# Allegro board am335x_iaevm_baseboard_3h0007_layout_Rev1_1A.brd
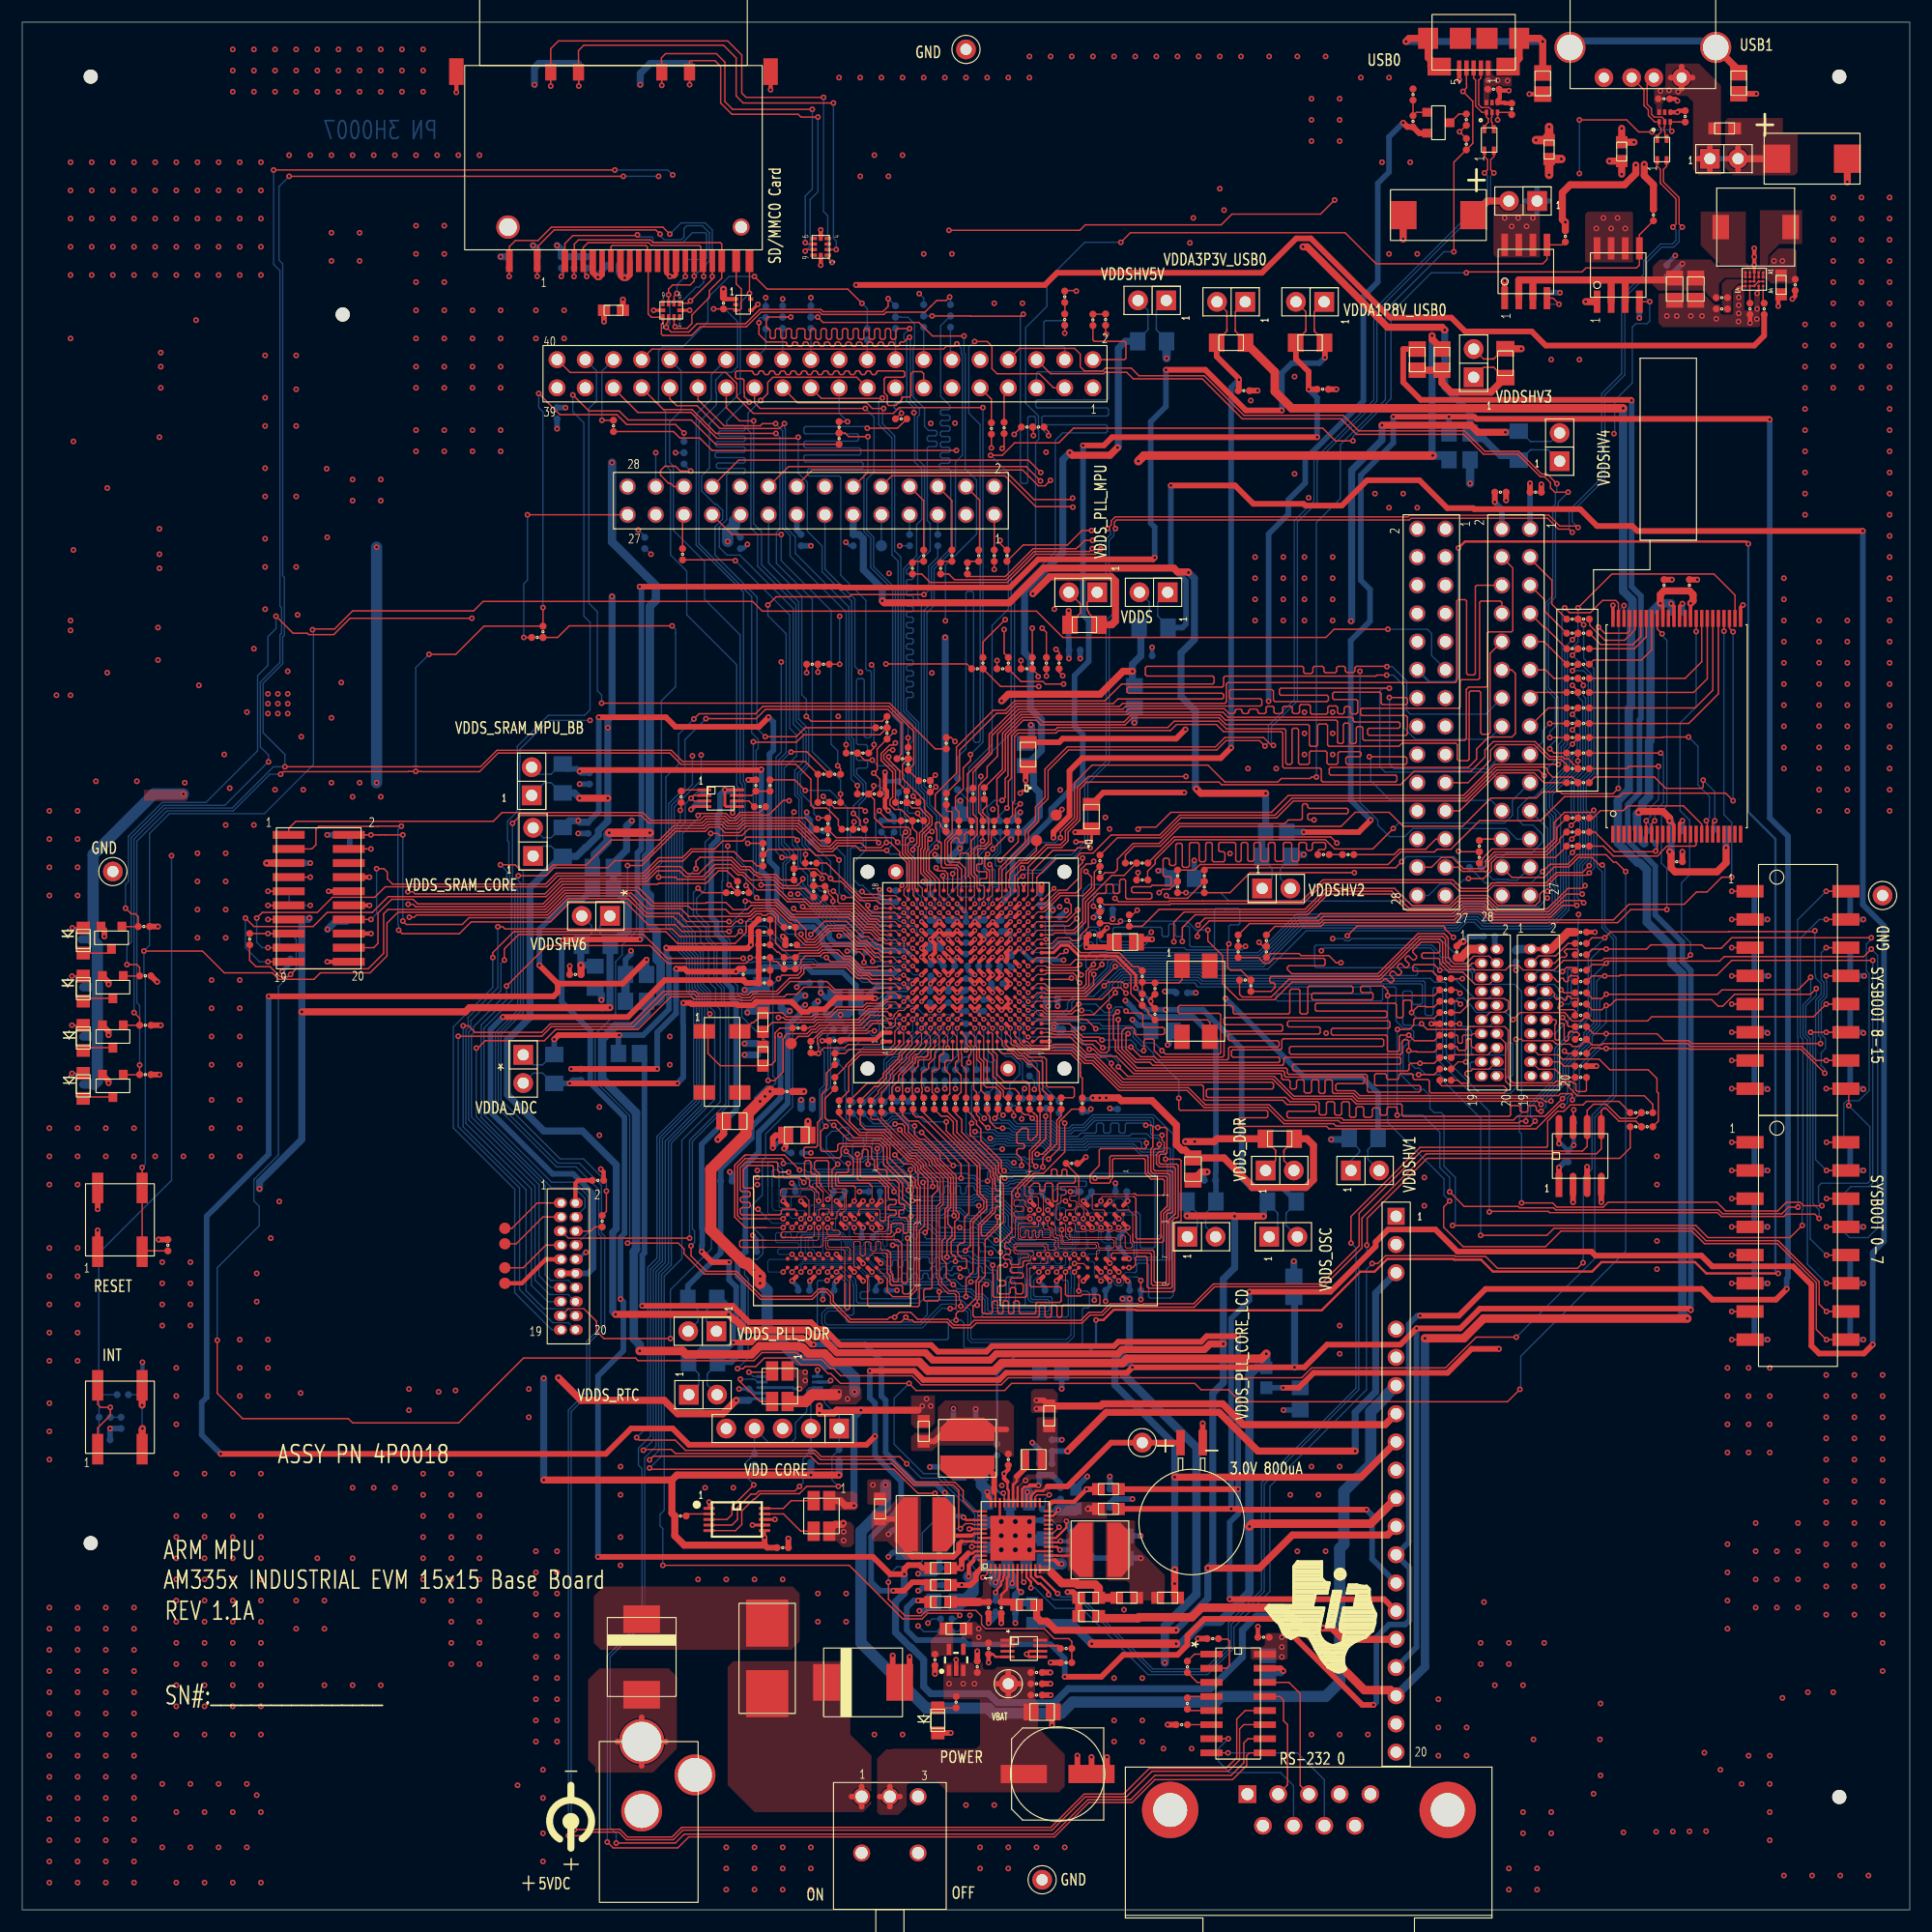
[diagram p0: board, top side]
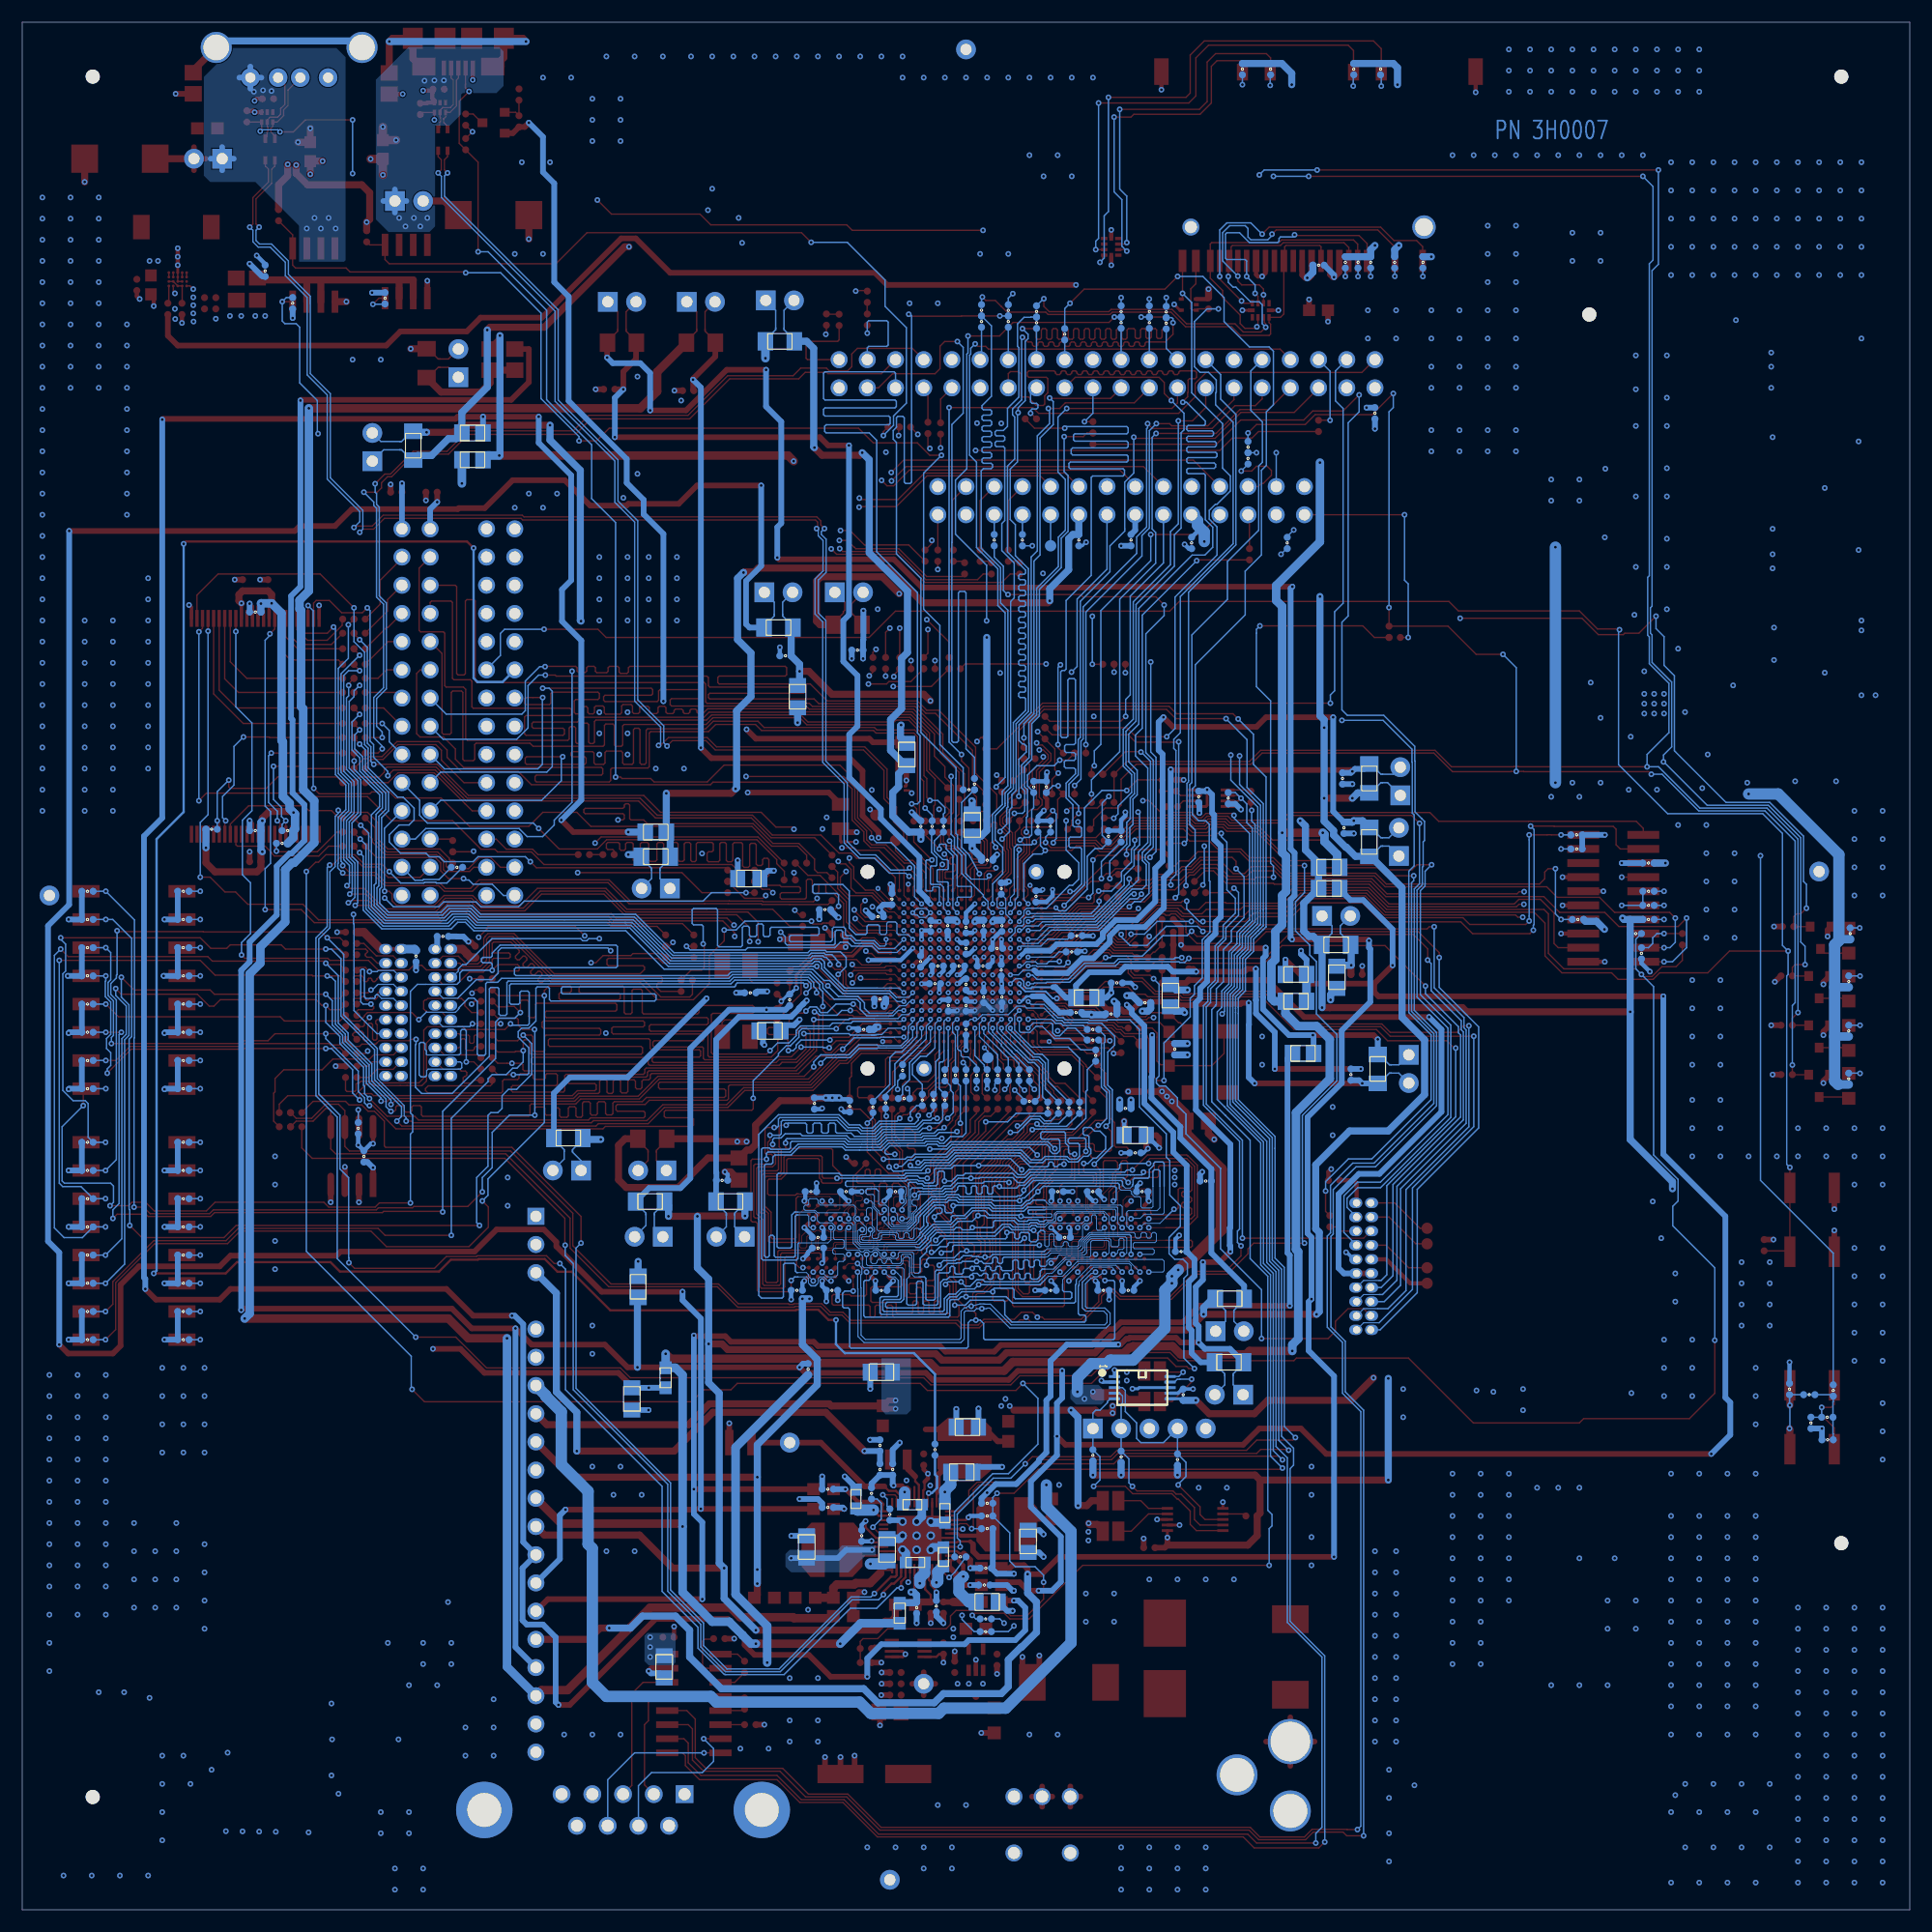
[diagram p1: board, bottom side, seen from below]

Outline 170 x 170 mm; copper layers: TOP, LY2_GND, LY3, LY4, LY5_GND, BOTTOM. Coordinates in mm from the lower left corner of the outline.
Outline path: 0,170 0,0 170,0 170,170 0,170

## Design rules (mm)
net group AM335X_DDR_A0: nets AM335X_DDR_A0 DDR_A0
net group AM335X_DDR_A1: nets AM335X_DDR_A1 DDR_A1
net group AM335X_DDR_A2: nets AM335X_DDR_A2 DDR_A2
net group AM335X_DDR_A3: nets AM335X_DDR_A3 DDR_A3
net group AM335X_DDR_A4: nets AM335X_DDR_A4 DDR_A4
net group AM335X_DDR_A5: nets AM335X_DDR_A5 DDR_A5
net group AM335X_DDR_A6: nets AM335X_DDR_A6 DDR_A6
net group AM335X_DDR_A7: nets AM335X_DDR_A7 DDR_A7
net group AM335X_DDR_A8: nets AM335X_DDR_A8 DDR_A8
net group AM335X_DDR_A9: nets AM335X_DDR_A9 DDR_A9
net group AM335X_DDR_A10: nets AM335X_DDR_A10 DDR_A10
net group AM335X_DDR_A11: nets AM335X_DDR_A11 DDR_A11
net group AM335X_DDR_A12: nets AM335X_DDR_A12 DDR_A12
net group AM335X_DDR_A13: nets AM335X_DDR_A13 DDR_A13
net group AM335X_DDR_A14: nets AM335X_DDR_A14 DDR_A14
net group AM335X_DDR_BA0: nets AM335X_DDR_BA0 DDR_BA0
net group AM335X_DDR_BA1: nets AM335X_DDR_BA1 DDR_BA1
net group AM335X_DDR_BA2: nets AM335X_DDR_BA2 DDR_BA2
net group AM335X_DDR_CASN: nets AM335X_DDR_CASN DDR_CASN
net group AM335X_DDR_CKE: nets AM335X_DDR_CKE DDR_CKE
net group AM335X_DDR_CLK: nets AM335X_DDR_CLK DDR_CLK
net group AM335X_DDR_CLKN: nets AM335X_DDR_CLKN DDR_CLKN
net group AM335X_DDR_CSN: nets AM335X_DDR_CSN DDR_CSN
net group AM335X_DDR_D0: nets AM335X_DDR_D0 DDR_D0
net group AM335X_DDR_D1: nets AM335X_DDR_D1 DDR_D1
net group AM335X_DDR_D2: nets AM335X_DDR_D2 DDR_D2
net group AM335X_DDR_D3: nets AM335X_DDR_D3 DDR_D3
net group AM335X_DDR_D4: nets AM335X_DDR_D4 DDR_D4
net group AM335X_DDR_D5: nets AM335X_DDR_D5 DDR_D5
net group AM335X_DDR_D6: nets AM335X_DDR_D6 DDR_D6
net group AM335X_DDR_D7: nets AM335X_DDR_D7 DDR_D7
net group AM335X_DDR_D8: nets AM335X_DDR_D8 DDR_D8
net group AM335X_DDR_D9: nets AM335X_DDR_D9 DDR_D9
net group AM335X_DDR_D10: nets AM335X_DDR_D10 DDR_D10
net group AM335X_DDR_D11: nets AM335X_DDR_D11 DDR_D11
net group AM335X_DDR_D12: nets AM335X_DDR_D12 DDR_D12
net group AM335X_DDR_D13: nets AM335X_DDR_D13 DDR_D13
net group AM335X_DDR_D14: nets AM335X_DDR_D14 DDR_D14
net group AM335X_DDR_D15: nets AM335X_DDR_D15 DDR_D15
net group AM335X_DDR_DQM0: nets AM335X_DDR_DQM0 DDR_DQM0
net group AM335X_DDR_DQM1: nets AM335X_DDR_DQM1 DDR_DQM1
net group AM335X_DDR_DQS0: nets AM335X_DDR_DQS0 DDR_DQS0
net group AM335X_DDR_DQS1: nets AM335X_DDR_DQS1 DDR_DQS1
net group AM335X_DDR_DQSN0: nets AM335X_DDR_DQSN0 DDR_DQSN0
net group AM335X_DDR_DQSN1: nets AM335X_DDR_DQSN1 DDR_DQSN1
net group AM335X_DDR_RASN: nets AM335X_DDR_RASN DDR_RASN
net group AM335X_DDR_WEN: nets AM335X_DDR_WEN DDR_WEN
net group AM335X_DDRODT: nets AM335X_DDRODT DDR_ODT
net group DP5: nets USB1_DM USB1_DP
net group JTAG: nets JTAG_TDI JTAG_TDO
net group 54: nets AM335X_GPMC_AD10 AM335X_GPMC_AD11 AM335X_LCD_DATA0 AM335X_LCD_DATA1 AM335X_LCD_DATA2 AM335X_LCD_DATA3 AM335X_LCD_DATA4 AM335X_LCD_DATA5 AM335X_LCD_DATA6 AM335X_LCD_DATA7 AM335X_LCD_DATA8 AM335X_LCD_DATA9 AM335X_LCD_DATA10 AM335X_LCD_DATA11 AM335X_LCD_DATA12 AM335X_LCD_DATA13 AM335X_LCD_DATA14 AM335X_LCD_DATA15 AM335X_LCD_HSYNC AM335X_LCD_PCLK AM335X_LCD_VSYNC
net group 69: nets AM335X_MII1_RXD0 AM335X_MII1_RXD1 AM335X_MII1_RXD2 AM335X_MII1_RXD3 AM335X_MII1_RXDV AM335X_MII1_TXD0 AM335X_MII1_TXD1 AM335X_MII1_TXD2 AM335X_MII1_TXD3 AM335X_MII1_TXEN
net group 69_CNTRL: nets AM335X_MII1_RXCLK AM335X_MII1_TXCLK EXP_MII1_RXCLK EXP_MII1_TXCLK
net group 69B: nets EXP_MII1_REFCLK EXP_MII1_RXD0 EXP_MII1_RXD1 EXP_MII1_RXD2 EXP_MII1_RXD3 EXP_MII1_RXDV EXP_MII1_TXD0 EXP_MII1_TXD1 EXP_MII1_TXD2 EXP_MII1_TXD3 EXP_MII1_TXEN
net group 70: nets AM335X_MII1_MDIO_CLK AM335X_MII1_MDIO_DATA EXP_MII1_MDIO_CLK EXP_MII1_MDIO_DATA
net group 80: nets AM335X_GPMC_A1 AM335X_GPMC_A2 AM335X_GPMC_A3 AM335X_GPMC_BE1N AM335X_GPMC_CLK AM335X_GPMC_CS3N
net group 81: nets EXP_GPMC_BE1N EXP_GPMC_CLK EXP_GPMC_CS3N GPMC_A1 GPMC_A2 GPMC_A3 SDIO_GPMC_BE1N SDIO_GPMC_CLK SDIO_GPMC_CS3N
net group 92: nets AM335X_GPMC_A0 AM335X_GPMC_A4 AM335X_GPMC_A6 AM335X_GPMC_A11 GPMC_A0 GPMC_A4 GPMC_A5 GPMC_A6 GPMC_A7 GPMC_A8 GPMC_A9 GPMC_A10 GPMC_A11
net group EXP_MMC0: nets EXP_MMC0_CLK EXP_MMC0_CMD EXP_MMC0_DAT0 EXP_MMC0_DAT1 EXP_MMC0_DAT2 EXP_MMC0_DAT3
net group H_SDMMC2: nets EXP_MMC1_CLK EXP_MMC1_CMD EXP_MMC1_DAT0 EXP_MMC1_DAT1 EXP_MMC1_DAT2 EXP_MMC1_DAT3 EXP_MMC1_DAT4 EXP_MMC1_DAT5 EXP_MMC1_DAT6 EXP_MMC1_DAT7
net group POWER_TRACE: nets VDDSHV1
net group SD_MMC_CC: nets MMC_CLK MMC_CMD MMC_D0 MMC_D1 MMC_D2 MMC_D3 MMC_D4 MMC_D5 MMC_D6 MMC_D7
net group USB: nets USB0_CONN_DM USB0_CONN_DP USB0_DM USB0_DP USB1_CONN_DM USB1_CONN_DP
nets with their own width: min track width 0.381; nets VDDSHV4 VDDSHV6

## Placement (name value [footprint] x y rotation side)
BT1  CoinBattery3.1V  [MS920SE-FL27E]  105.32 42.07 90 top
C1  0.01uF  [SM-7351-CAP-0402]  64.05 100.24 270 bottom
C2  25pF  [SM-7351-CAP-0603]  66.71 79.92 90 top
C3  25pF  [SM-7351-CAP-0603]  66.71 76.87 270 top
C4  18pF  [SM-7351-CAP-0402]  102.02 80.66 90 top
C5  18pF  [SM-7351-CAP-0402]  102.02 82.97 270 top
C9  0.1uF  [SM-7351-CAP-0402]  68.62 85.25 270 top
C10  0.001uF  [SM-7351-CAP-0402]  69.63 85.25 270 top
C11  0.1uF  [SM-7351-CAP-0402]  66.84 86.91 180 top
C12  0.001uF  [SM-7351-CAP-0402]  66.84 88.05 180 top
C13  0.1uF  [SM-7351-CAP-0402]  66.84 84.62 180 top
C14  0.001uF  [SM-7351-CAP-0402]  66.84 85.76 180 top
C16  0.01uF  [SM-7351-CAP-0402]  66.2 77.51 90 bottom
C17  0.01uF  [SM-7351-CAP-0402]  68.87 73.7 0 top
C19  0.01uF  [SM-7351-CAP-0402]  83.48 85 0 bottom
C23  0.01uF  [SM-7351-CAP-0402]  70.65 72.17 0 bottom
C24  0.01uF  [SM-7351-CAP-0402]  85 83.35 270 bottom
C25  0.01uF  [SM-7351-CAP-0402]  92.75 82.02 0 bottom
C27  0.01uF  [SM-7351-CAP-0402]  81.76 88.62 270 bottom
C28  0.01uF  [SM-7351-CAP-0402]  49.82 84.24 180 top
C29  0.01uF  [SM-7351-CAP-0402]  94.21 79.29 0 bottom
C30  0.01uF  [SM-7351-CAP-0402]  71.41 83.48 0 bottom
C31  0.01uF  [SM-7351-CAP-0402]  87.79 83.41 180 bottom
C32  0.01uF  [SM-7351-CAP-0402]  104.43 82.59 0 bottom
C34  0.01uF  [SM-7351-CAP-0402]  85 86.59 270 bottom
C35  0.01uF  [SM-7351-CAP-0402]  85.64 85 180 bottom
C36  0.01uF  [SM-7351-CAP-0402]  87.54 85 180 bottom
C41  0.01uF  [SM-7351-CAP-0402]  82.21 86.59 0 bottom
C42  0.01uF  [SM-7351-CAP-0402]  83.41 88.62 270 bottom
C43  0.01uF  [SM-7351-CAP-0402]  83.1 94.53 180 bottom
C45  0.01uF  [SM-7351-CAP-0402]  89.06 97.57 90 bottom
C46  0.01uF  [SM-7351-CAP-0402]  86.65 88.63 270 bottom
C47  0.01uF  [SM-7351-CAP-0402]  78.7 91.27 90 bottom
C48  0.01uF  [SM-7351-CAP-0402]  91.67 91.03 90 bottom
C50  0.01uF  [SM-7351-CAP-0402]  92.94 89.45 0 bottom
C52  0.01uF  [SM-7351-CAP-0402]  68.87 81.7 180 bottom
C53  0.01uF  [SM-7351-CAP-0402]  81.83 84.62 270 bottom
C56  0.01uF  [SM-7351-CAP-0402]  71.92 80.68 0 bottom
C60  1uF  [SM-7351-CAP-0402]  69.25 86.91 180 top
C61  0.01uF  [SM-7351-CAP-0402]  117.13 136.94 0 top
C62  0.01uF  [SM-7351-CAP-0402]  110.02 136.82 0 top
C63  0.01uF  [SM-7351-CAP-0402]  50.33 75.22 90 bottom
C64  0.01uF  [SM-7351-CAP-0402]  106.97 65.7 180 bottom
C65  1uF  [SM-7351-CAP-0402]  75.09 80.81 180 bottom
C66  0.01uF  [SM-7351-CAP-0402]  65.63 59.28 0 bottom
C67  0.01uF  [SM-7351-CAP-0402]  100.88 81.95 90 bottom
C68  0.01uF  [SM-7351-CAP-0402]  51.09 101.89 270 bottom
C69  0.01uF  [SM-7351-CAP-0402]  50.96 97.45 270 bottom
C70  0.01uF  [SM-7351-CAP-0402]  94.78 113.45 0 bottom
C71  1uF  [SM-7351-CAP-0402]  75.03 87.73 180 bottom
C72  1uF  [SM-7351-CAP-0402]  75.48 86.27 180 bottom
C73  0.01uF  [SM-7351-CAP-0402]  63.41 65.63 0 bottom
C76  0.01uF  [SM-7351-CAP-0402]  83.41 82.21 90 bottom
C77  0.01uF  [SM-7351-CAP-0402]  81.76 82.21 90 bottom
C78  0.01uF  [SM-7351-CAP-0402]  86.59 81.44 90 bottom
C79  0.01uF  [SM-7351-CAP-0402]  85 81.44 90 bottom
C80  0.01uF  [SM-7351-CAP-0402]  95.48 72.36 270 bottom
C82  0.01uF  [SM-7351-CAP-0402]  98.65 72.62 270 bottom
C83  0.01uF  [SM-7351-CAP-0402]  85 88.49 90 bottom
C84  100uF  [SM-7351-CAP-SMDCAN]  93.26 12.23 180 top
C85  0.1uF  [SM-7351-CAP-0402]  91.35 20.36 0 top
C86  0.1uF  [SM-7351-CAP-0402]  91.35 21.37 0 top
C88  1uF  [SM-7351-CAP-0402]  91.35 19.34 0 top
C89  0.01uF  [SM-7351-CAP-0402]  101.26 112.94 0 bottom
C90  0.01uF  [SM-7351-CAP-0402]  89.09 85.41 270 bottom
C91  2.2uF  [SM-7351-CAP-0402]  92.75 41.82 90 bottom
C92  0.01uF  [SM-7351-CAP-0402]  96.56 87.79 0 top
C93  0.01uF  [SM-7351-CAP-0402]  97.7 90.08 0 bottom
C94  0.01uF  [SM-7351-CAP-0402]  88.18 88.61 90 bottom
C96  0.01uF  [SM-7351-CAP-0402]  81.83 91.99 90 bottom
C97  2.2uF  [SM-7351-CAP-0402]  91.6 39.66 90 bottom
C98  0.1uF  [SM-7351-CAP-0402]  94.4 33.69 270 bottom
C101  2.2uF  [SM-7351-CAP-0402]  97.45 36.23 0 bottom
C102  2.2uF  [SM-7351-CAP-0402]  97.45 37.88 0 bottom
C103  2.2uF  [SM-7351-CAP-0402]  88.18 27.22 270 top
C104  2.2uF  [SM-7351-CAP-0402]  89.45 27.22 270 bottom
C107  2.2uF  [SM-7351-CAP-0402]  87.03 27.22 270 top
C108  2.2uF  [SM-7351-CAP-0402]  87.67 27.34 270 bottom
C109  2.2uF  [SM-7351-CAP-0402]  83.22 30.77 180 bottom
C110  2.2uF  [SM-7351-CAP-0402]  83.35 29.25 180 bottom
C111  0.01uF  [SM-7351-CAP-0402]  87.03 23.53 270 top
C112  1uF  [SM-7351-CAP-0402]  86.02 21.88 90 top
C113  1uF  [SM-7351-CAP-0402]  82.21 22.52 270 top
C114  0.01uF  [SM-7351-CAP-0402]  94.02 22.26 180 top
C115  0.01uF  [SM-7351-CAP-0402]  23.53 94.27 0 bottom
C116  0.01uF  [SM-7351-CAP-0402]  139.23 67.86 270 bottom
C117  1uF  [SM-7351-CAP-0402]  13.12 59.85 90 top
C118  1uF  [SM-7351-CAP-0402]  7.4 42.33 0 bottom
C125  0.01uF  [SM-7351-CAP-0402]  69.76 68.17 0 bottom
C126  0.01uF  [SM-7351-CAP-0402]  72.62 55.79 180 bottom
C127  0.1uF  [SM-7351-CAP-0402]  149.01 97.19 0 bottom
C128  0.01uF  [SM-7351-CAP-0402]  149.01 94.4 0 top
C129  0.01uF  [SM-7351-CAP-0402]  149.01 116.88 0 bottom
C130  0.01uF  [SM-7351-CAP-0402]  150.15 119.29 90 top
C131  0.1uF  [SM-7351-CAP-0402]  147.87 119.29 90 top
C132  0.1uF  [SM-7351-CAP-0402]  133.13 127.67 0 top
C133  0.1uF  [SM-7351-CAP-0402]  136.31 127.67 0 top
C134  0.1uF  [SM-7351-CAP-0402]  70.14 123.35 270 bottom
C135  0.1uF  [SM-7351-CAP-0402]  48.17 134.78 270 bottom
C136  0.01uF  [SM-7351-CAP-0402]  134.53 85.89 270 bottom
C137  0.01uF  [SM-7351-CAP-0402]  140.37 88.05 0 top
C138  0.01uF  [SM-7351-CAP-0402]  132.12 87.67 180 bottom
C139  0.01uF  [SM-7351-CAP-0402]  129.2 86.27 90 top
C140  0.01uF  [SM-7351-CAP-0402]  51.85 65.7 0 top
C141  0.1uF  [SM-7351-CAP-0402]  64.68 123.1 270 bottom
C148  0.1uF  [SM-7351-CAP-0402]  74.84 123.35 270 bottom
C155  0.01uF  [SM-7351-CAP-0402]  77.38 55.79 0 bottom
C156  0.01uF  [SM-7351-CAP-0402]  98.34 60.55 0 bottom
C174  0.01uF  [SM-7351-CAP-0402]  92.62 55.79 180 bottom
C175  0.01uF  [SM-7351-CAP-0402]  111.8 24.55 180 top
C176  0.1uF  [SM-7351-CAP-0402]  104.94 21.88 270 top
C177  0.1uF  [SM-7351-CAP-0402]  107.23 24.42 180 top
C178  0.1uF  [SM-7351-CAP-0402]  104.94 18.58 270 top
C179  0.1uF  [SM-7351-CAP-0402]  104.43 16.67 180 top
C180  0.1uF  [SM-7351-CAP-0402]  53.25 148.12 180 bottom
C181  0.01uF  [SM-7351-CAP-0402]  100.24 55.79 0 bottom
C182  150uF  [SM-7351-CAP-2917]  127.55 152.63 0 top
C183  0.01uF  [SM-7351-CAP-0402]  132.5 163.97 0 top
C184  2.2uF  [SM-7351-CAP-0402]  148.12 147.61 90 bottom
C185  150uF  [SM-7351-CAP-2917]  161.2 157.71 180 top
C186  0.01uF  [SM-7351-CAP-0402]  147.87 163.11 0 top
C187  0.1uF  [SM-7351-CAP-0402]  159.68 146.34 270 top
C188  0.01uF  [SM-7351-CAP-0402]  91.35 64.68 0 bottom
C189  0.01uF  [SM-7351-CAP-0402]  97.07 55.79 180 bottom
C195  0.01uF  [SM-7351-CAP-0402]  98.34 59.6 0 bottom
C202  0.01uF  [SM-7351-CAP-0402]  95.8 64.68 180 bottom
C215  0.01uF  [SM-7351-CAP-0402]  65.44 46.39 90 bottom
C216  0.01uF  [SM-7351-CAP-0402]  98.97 64.68 180 bottom
C217  0.01uF  [SM-7351-CAP-0402]  76.75 64.68 180 bottom
C218  0.01uF  [SM-7351-CAP-0402]  69.13 64.68 0 bottom
C219  0.01uF  [SM-7351-CAP-0402]  73.57 64.68 180 bottom
C220  0.01uF  [SM-7351-CAP-0402]  70.4 55.79 180 bottom
C221  0.01uF  [SM-7351-CAP-0402]  76.11 60.55 0 bottom
C222  0.01uF  [SM-7351-CAP-0402]  68.49 32.61 0 top
C232  10uF  [SM-7351-CAP-0805]  64.17 71.03 180 top
C233  10uF  [SM-7351-CAP-0805]  105.45 66.71 270 top
C234  10uF  [SM-7351-CAP-0805]  91.86 17.82 0 top
C235  10uF  [SM-7351-CAP-0805]  92.62 48.42 0 bottom
C236  10uF  [SM-7351-CAP-0805]  83.1 27.72 180 bottom
C237  10uF  [SM-7351-CAP-0805]  84.87 43.47 180 bottom
C238  10uF  [SM-7351-CAP-0805]  85.38 39.41 180 bottom
C239  10uF  [SM-7351-CAP-0805]  79.41 33.18 270 bottom
C240  10uF  [SM-7351-CAP-0805]  92.11 32.42 90 bottom
C241  10uF  [SM-7351-CAP-0805]  99.35 32.68 90 bottom
C245  10uF  [SM-7351-CAP-0805]  112.18 21.88 270 bottom
C246  10uF  [SM-7351-CAP-0805]  66.59 82.33 90 bottom
C247  10uF  [SM-7351-CAP-0805]  51.6 83.98 270 bottom
C249  10uF  [SM-7351-CAP-0805]  100.16 109.26 270 bottom
C250  4.7uF  [SM-7351-CAP-0603]  89.83 36.49 180 bottom
C251  4.7uF  [SM-7351-CAP-0603]  94.91 36.99 90 bottom
C252  4.7uF  [SM-7351-CAP-0603]  89.57 31.28 0 bottom
C253  4.7uF  [SM-7351-CAP-0603]  86.91 35.72 270 bottom
C254  4.7uF  [SM-7351-CAP-0603]  87.03 31.79 90 bottom
C255  4.7uF  [SM-7351-CAP-0603]  53.25 144.06 180 top
C257  10uF  [SM-7351-CAP-0805]  90.33 104.05 90 bottom
C258  10uF  [SM-7351-CAP-0805]  102.65 79.16 0 bottom
C259  10uF  [SM-7351-CAP-0805]  99.35 87.16 0 top
C260  0.1uF  [SM-7351-CAP-0402]  24.17 86.14 270 bottom
C261  10uF  [SM-7351-CAP-0805]  115.1 46.01 270 bottom
C262  4.7uF  [SM-7351-CAP-0603]  137.51 158.53 270 top
C263  4.7uF  [SM-7351-CAP-0603]  158.41 146.34 270 top
C264  0.1uF  [SM-7351-CAP-0402]  155.61 144.18 270 top
C265  4.7uF  [SM-7351-CAP-0603]  144.06 158.34 270 top
C266  22uF  [SM-7351-CAP-0805]  69.76 69.76 0 top
C267  22uF  [SM-7351-CAP-0805]  69.76 69.76 0 bottom
C269  22uF  [SM-7351-CAP-0805]  150.72 145.96 270 top
C270  22uF  [SM-7351-CAP-0805]  148.82 145.96 270 top
C273  10uF  [SM-7351-CAP-0805]  104.56 92.87 0 bottom
C274  10uF  [SM-7351-CAP-0805]  84.44 97.7 90 bottom
D1  -  [B520C-13-F]  55.79 22.77 270 top
D2  -  [SMCJ15CA]  75.73 20.48 0 top
D3  Green LED  [SM_LED_0805]  82.46 17.06 270 top
D4  Green LED  [SM_LED_0805]  5.5 87.29 270 top
D5  Green LED  [SM_LED_0805]  5.5 82.97 270 top
D6  Green LED  [SM_LED_0805]  5.5 78.52 270 top
D7  Green LED  [SM_LED_0805]  5.5 74.21 270 top
D9  GDZT2R5.1  [GMD2_2PIN]  96.05 96.18 90 top
D10  GDZT2R5.1  [GMD2_2PIN]  90.46 101 180 top
F1  Fuse 4A  [SMDFUSEBLK]  67.09 22.64 270 top
FB1  150OHM800mA  [SM-7351-IND-0805]  55.28 81.83 0 bottom
FB2  150OHM800mA  [SM-7351-IND-0805]  55.28 84.24 0 bottom
FB3  150OHM800mA  [SM-7351-IND-0805]  129.45 130.59 180 bottom
FB4  150OHM800mA  [SM-7351-IND-0805]  129.45 133.01 180 bottom
FB5  150OHM800mA  [SM-7351-IND-0805]  112.94 97.07 0 bottom
FB6  150OHM800mA  [SM-7351-IND-0805]  114.53 56.11 270 bottom
FB7  150OHM800mA  [SM-7351-IND-0805]  52.3 93.89 180 bottom
FB8  150OHM800mA  [SM-7351-IND-0805]  52.3 91.99 180 bottom
FB9  150OHM800mA  [SM-7351-IND-0805]  54.65 77.13 0 bottom
FB10  150OHM800mA  [SM-7351-IND-0805]  74.14 82.14 180 bottom
FB14  150OHM800mA  [SM-7351-IND-0805]  136.94 164.48 90 top
FB19  150OHM800mA  [SM-7351-IND-0805]  154.6 164.5 90 top
FB20  150OHM800mA  [SM-7351-IND-0805]  125.64 139.61 90 top
FB21  150OHM800mA  [SM-7351-IND-0805]  127.86 139.61 90 top
J1  Power Jack RAPC712  [RAPC712]  55.79 15.15 90 top
J2  CTI JTAG  [HEADER10X2]  26.71 91.1 270 top
J3  Header_14x2  [JUMP2X14-6040-1]  135.8 124.37 90 top
J4  Header_14x2  [JUMP2X14-6040-1]  128.18 124.37 90 top
J5  Header_20x2  [JUMP2X20-6040-1]  96.43 137.07 0 top
J6  Header_14x2  [JUMP2X14-6040-1]  87.54 125.64 0 top
J7  Header_10x2  [HEADER_10X2_TH]  135.93 86.52 270 top
J8  Header_10x2  [HEADER_10X2_TH]  131.48 86.52 270 top
J9  Header_10x2  [HEADER_10X2_TH]  48.55 63.66 270 top
J12  Conn_DB9M_TH  [NORCOMP_DB9M_TH]  110.4 10.41 180 top
J13  MHC-W21-601  [MHC-W21-601-LF]  53.25 148.5 180 top
J14  USB_MicroAB  [ZX62-AB-5PA]  130.72 165.87 180 top
J17  HEADER 5  [HEADER_5X1]  73.57 43.34 180 top
J18  USB A  [USB_STD_A_TH]  149.45 165.01 180 top
J19  Header20x1_wkey  [HEADER20X1_0_100IN]  123.74 62.46 270 top
J20  HEADER 2  [HEADER_2X1]  111.99 66.59 270 top
J21  HEADER 2  [HEADER_2X1]  103.16 118.66 90 top
J22  HEADER 2  [HEADER_2X1]  96.81 118.66 90 top
J23  HEADER 2  [HEADER_2X1]  45.88 100.37 0 top
J24  HEADER 2  [HEADER_2X1]  104.94 60.62 270 top
J25  HEADER 2  [HEADER_2X1]  46.01 94.91 0 top
J26  HEADER 2  [HEADER_2X1]  119.67 66.59 270 top
J27  HEADER 2  [HEADER_2X1]  45.12 77 180 top
J28  HEADER 2  [HEADER_2X1]  117.26 144.82 90 top
J29  HEADER 2  [HEADER_2X1]  112.31 60.62 270 top
J30  HEADER 2  [HEADER_2X1]  138.47 130.47 0 top
J31  HEADER 2  [HEADER_2X1]  110.15 144.82 90 top
J32  HEADER 2  [HEADER_2X1]  103.03 144.94 90 top
J33  HEADER 2  [HEADER_2X1]  62.52 52.11 90 top
J34  HEADER 2  [HEADER_2X1]  52.93 89.51 90 top
J35  HEADER 2  [HEADER_2X1]  60.04 46.39 270 top
J36  HEADER 2  [HEADER_2X1]  136.44 153.9 90 top
J37  HEADER 2  [HEADER_2X1]  151.99 157.71 270 top
J38  HEADER 2  [HEADER_2X1]  111.67 91.99 270 top
J39  HEADER 2  [HEADER_2X1]  130.72 138.02 0 top
L2  2.2uH  [VLCF5020T]  85.13 41.57 90 top
L3  2.2uH  [VLCF5020T]  81.32 34.71 180 top
L4  2.2uH  [VLCF5020T]  97.07 32.42 0 top
L5  ACM2012  [ACM2012H]  132.12 159.4 90 top
L6  ACM2012  [ACM2012H]  147.67 158.53 90 top
L8  4.7uH  [CHKFOOTPRINT]  91.1 40.55 0 top
L9  4.7uH  [SMD_SLF7055T]  156.12 151.55 180 top
NOREF  -  [unnamed]  163.65 165.1 90 top
NOREF#2  -  [#2]  170 0 90 top
NOREF#3  -  [unnamed]  6.17 165.1 90 top
NOREF#4  -  [unnamed]  28.87 143.67 0 top
NOREF#5  -  [#2]  117.45 26.39 0 top
NOREF#6  -  [#2]  0 170 0 top
NOREF#7  -  [unnamed]  6.17 33.02 90 top
NOREF#8  -  [unnamed]  163.65 10.16 90 top
Q1  BSS138  [SOT23-3]  8.04 87.54 180 top
Q2  BSS138  [SOT23-3]  8.17 83.1 180 top
Q3  BSS138  [SOT23-3]  8.17 78.65 180 top
Q4  BSS138  [SOT23-3]  8.17 74.21 180 top
Q5  BSS84  [SOT23-3]  127.55 160.95 270 top
R1  0  [SM-7351-RES-0402]  59.35 100.24 270 top
R2  100K  [SM-7351-RES-0402]  66.08 101.26 270 top
R3  0  [SM-7351-RES-0402]  66.46 99.35 0 top
R4  100K  [SM-7351-RES-0402]  61.38 100.11 90 bottom
R5  0  [SM-7351-RES-0402]  69.89 79.41 180 top
R6  10K  [SM-7351-RES-0402]  24.68 87.92 0 bottom
R7  1M  [SM-7351-RES-0402]  100.88 81.98 270 top
R8  0  [SM-7351-RES-0402]  100.88 84.06 270 top
R9  0  [SM-7351-RES-0402]  67.35 101.26 90 top
R10  0  [SM-7351-RES-0402]  69.13 88.49 0 top
R11  22  [SM-7351-RES-0402]  77.38 72.36 270 top
R12  22  [SM-7351-RES-0402]  76.43 72.36 270 top
R13  22  [SM-7351-RES-0402]  80.24 72.62 270 top
R14  22  [SM-7351-RES-0402]  80.24 75.16 270 bottom
R15  22  [SM-7351-RES-0402]  73.57 72.36 270 top
R16  22  [SM-7351-RES-0402]  90.72 72.62 270 top
R17  22  [SM-7351-RES-0402]  93.57 72.62 270 top
R18  22  [SM-7351-RES-0402]  77.63 72.24 270 bottom
R19  22  [SM-7351-RES-0402]  85 75.16 270 bottom
R20  22  [SM-7351-RES-0402]  87.86 72.62 270 top
R21  22  [SM-7351-RES-0402]  83.1 72.62 270 top
R22  50  [SM-7351-RES-0402]  83.1 75.16 90 bottom
R23  124K  [SM-7351-RES-0402]  130.06 161.23 90 top
R30  0  [SM-7351-RES-0402]  66.84 89.19 0 top
R31  22  [SM-7351-RES-0402]  76.68 72.24 270 bottom
R32  0.05ohm1% Sense  [SM_RES_LVK12]  68.24 47.15 270 top
R33  22  [SM-7351-RES-0402]  73.57 78.33 180 bottom
R34  22  [SM-7351-RES-0402]  75.48 72.36 270 top
R35  22  [SM-7351-RES-0402]  73.19 74.46 270 top
R36  22  [SM-7351-RES-0402]  74.78 72.24 270 bottom
R37  22  [SM-7351-RES-0402]  79.29 72.62 270 top
R38  22  [SM-7351-RES-0402]  73.32 76.94 270 bottom
R39  22  [SM-7351-RES-0402]  74.52 72.36 270 top
R40  22  [SM-7351-RES-0402]  79.29 72.81 0 bottom
R41  22  [SM-7351-RES-0402]  81.19 72.62 270 top
R42  22  [SM-7351-RES-0402]  75.73 72.24 270 bottom
R43  22  [SM-7351-RES-0402]  81.19 75.16 270 bottom
R44  22  [SM-7351-RES-0402]  82.14 75.16 270 bottom
R45  0  [SM-7351-RES-0402]  64.93 84.24 270 top
R46  0.05ohm1% Sense  [SM_RES_LVK12]  71.98 35.47 270 top
R47  22  [SM-7351-RES-0402]  73.57 79.29 180 bottom
R48  10K  [SM-7351-RES-0402]  71.03 77.7 90 top
R49  22  [SM-7351-RES-0402]  78.33 72.62 270 top
R50  150  [SM-7351-RES-0402]  84.11 18.71 90 top
R51  0  [SM-7351-RES-0402]  66.84 83.48 180 top
R53  0  [SM-7351-RES-0402]  92.75 39.66 90 bottom
R54  10K  [SM-7351-RES-0402]  83.1 36.61 0 bottom
R55  0  [SM-7351-RES-0402]  131.23 94.78 90 top
R56  0  [SM-7351-RES-0402]  69.51 93.26 90 top
R57  0  [SM-7351-RES-0402]  83.1 35.47 180 bottom
R58  0  [SM-7351-RES-0402]  145.33 71.79 0 top
R59  0  [SM-7351-RES-0402]  145.33 70.52 0 top
R60  0  [SM-7351-RES-0402]  93.51 37.5 90 bottom
R61  0  [SM-7351-RES-0402]  79.79 103.16 90 top
R62  0  [SM-7351-RES-0402]  79.16 99.73 0 top
R63  0  [SM-7351-RES-0402]  87.79 41.44 90 bottom
R64  0  [SM-7351-RES-0402]  91.86 35.6 270 bottom
R65  10K  [SM-7351-RES-0402]  83.1 34.33 0 bottom
R66  0  [SM-7351-RES-0402]  81.27 101.69 0 top
R68  0  [SM-7351-RES-0402]  99.22 48.68 90 bottom
R69  1K  [SM-7351-RES-0402]  94.02 23.53 180 top
R70  4.7K  [SM-7351-RES-0402]  29.88 89.19 180 bottom
R71  4.7K  [SM-7351-RES-0402]  23.53 89.19 0 bottom
R72  10K  [SM-7351-RES-0402]  139.74 70.4 270 bottom
R73  0  [SM-7351-RES-0402]  30.01 95.54 0 bottom
R74  0  [SM-7351-RES-0402]  23.53 91.73 0 bottom
R75  0  [SM-7351-RES-0402]  23.53 90.46 0 bottom
R76  0  [SM-7351-RES-0402]  66.71 94.53 90 top
R77  0  [SM-7351-RES-0402]  64.43 92.11 270 top
R78  0  [SM-7351-RES-0402]  71.28 91.73 90 top
R79  4.7K  [SM-7351-RES-0402]  30.01 96.81 0 bottom
R80  150  [SM-7351-RES-0402]  5.37 87.92 270 bottom
R81  150  [SM-7351-RES-0402]  5.5 83.6 270 bottom
R82  150  [SM-7351-RES-0402]  5.5 79.16 270 bottom
R83  150  [SM-7351-RES-0402]  5.5 74.84 270 bottom
R84  0  [SM-7351-RES-0402]  75.73 104.18 180 top
R85  0  [SM-7351-RES-0402]  72.17 112.18 180 top
R86  100K  [SM-7351-RES-0402]  10.96 88.56 180 top
R87  0  [SM-7351-RES-0402]  76.75 100.49 180 top
R88  0  [SM-7351-RES-0402]  77.89 105.96 90 top
R89  0  [SM-7351-RES-0402]  72.17 99.73 0 top
R90  0  [SM-7351-RES-0402]  72.17 102.27 0 top
R91  0  [SM-7351-RES-0402]  74.33 97.32 0 top
R92  0  [SM-7351-RES-0402]  46.9 115.1 270 top
R93  100K  [SM-7351-RES-0402]  11.09 84.11 180 top
R94  100K  [SM-7351-RES-0402]  11.09 75.22 180 top
R95  100K  [SM-7351-RES-0402]  11.09 79.67 180 top
R96  9.1K  [SM-7351-RES-0402]  164.12 69.13 0 bottom
R97  9.1K  [SM-7351-RES-0402]  164.12 66.59 0 bottom
R98  9.1K  [SM-7351-RES-0402]  164.12 64.05 0 bottom
R99  9.1K  [SM-7351-RES-0402]  164.12 61.51 0 bottom
R100  9.1K  [SM-7351-RES-0402]  164.12 58.97 0 bottom
R101  9.1K  [SM-7351-RES-0402]  164.12 56.43 0 bottom
R102  100K  [SM-7351-RES-0402]  164.12 53.89 0 bottom
R103  100K  [SM-7351-RES-0402]  164.12 51.35 0 bottom
R104  100K  [SM-7351-RES-0402]  164.12 91.73 0 bottom
R105  100K  [SM-7351-RES-0402]  164.12 89.19 0 bottom
R106  100K  [SM-7351-RES-0402]  164.12 86.65 0 bottom
R107  100K  [SM-7351-RES-0402]  164.12 84.11 0 bottom
R108  100K  [SM-7351-RES-0402]  164.12 81.57 0 bottom
R109  100K  [SM-7351-RES-0402]  164.12 79.03 0 bottom
R110  100K  [SM-7351-RES-0402]  164.12 76.49 0 bottom
R111  9.1K  [SM-7351-RES-0402]  164.12 73.95 0 bottom
R112  1K  [SM-7351-RES-0402]  8.9 43.85 90 bottom
R113  0  [SM-7351-RES-0402]  6.9 46.77 270 bottom
R114  1K  [SM-7351-RES-0402]  155.49 69.13 180 bottom
R115  1K  [SM-7351-RES-0402]  155.49 66.59 180 bottom
R116  1K  [SM-7351-RES-0402]  155.49 64.05 180 bottom
R117  1K  [SM-7351-RES-0402]  155.49 61.51 180 bottom
R118  1K  [SM-7351-RES-0402]  155.49 58.97 180 bottom
R119  1K  [SM-7351-RES-0402]  155.49 56.43 180 bottom
R120  10K  [SM-7351-RES-0402]  155.49 53.89 180 bottom
R121  10K  [SM-7351-RES-0402]  155.49 51.35 180 bottom
R122  10K  [SM-7351-RES-0402]  155.49 91.73 180 bottom
R123  10K  [SM-7351-RES-0402]  155.49 89.19 180 bottom
R124  10K  [SM-7351-RES-0402]  155.49 86.65 180 bottom
R125  10K  [SM-7351-RES-0402]  155.49 84.11 180 bottom
R126  10K  [SM-7351-RES-0402]  155.49 81.57 180 bottom
R127  10K  [SM-7351-RES-0402]  155.49 79.03 180 bottom
R128  10K  [SM-7351-RES-0402]  155.49 76.49 180 bottom
R129  1K  [SM-7351-RES-0402]  155.49 73.95 180 bottom
R130  10K  [SM-7351-RES-0402]  152.95 97.32 0 bottom
R131  10K  [SM-7351-RES-0402]  146.09 97.19 180 bottom
R132  10K  [SM-7351-RES-0402]  146.6 96.05 180 bottom
R133  0  [SM-7351-RES-0402]  140.63 102.78 180 top
R134  0  [SM-7351-RES-0402]  140.63 104.18 180 top
R135  0  [SM-7351-RES-0402]  140.63 97.07 180 top
R136  0  [SM-7351-RES-0402]  140.63 95.8 180 top
R137  0  [SM-7351-RES-0402]  140.63 98.34 180 top
R138  0  [SM-7351-RES-0402]  140.63 105.57 180 top
R139  0  [SM-7351-RES-0402]  140.63 101.51 180 top
R140  0  [SM-7351-RES-0402]  140.63 106.84 180 top
R141  0  [SM-7351-RES-0402]  140.63 108.24 180 top
R142  0  [SM-7351-RES-0402]  140.63 109.64 180 top
R143  0  [SM-7351-RES-0402]  140.63 110.91 180 top
R144  0  [SM-7351-RES-0402]  140.63 112.18 180 top
R145  0  [SM-7351-RES-0402]  140.63 113.58 180 top
R146  0  [SM-7351-RES-0402]  140.63 114.97 180 top
R147  0  [SM-7351-RES-0402]  140.63 116.24 180 top
R148  0  [SM-7351-RES-0402]  106.46 93.13 270 top
R149  0  [SM-7351-RES-0402]  104.05 93.13 270 top
R150  0  [SM-7351-RES-0402]  109.51 87.29 270 top
R151  0  [SM-7351-RES-0402]  110.15 83.73 0 top
R152  0  [SM-7351-RES-0402]  112.05 87.29 270 top
R153  0  [SM-7351-RES-0402]  97.07 90.38 270 top
R154  0  [SM-7351-RES-0402]  99.86 94.27 0 top
R155  0  [SM-7351-RES-0402]  97.07 94.47 270 top
R156  0  [SM-7351-RES-0402]  7.43 44.36 0 bottom
R157  0  [SM-7351-RES-0402]  139.61 116.24 180 top
R158  0  [SM-7351-RES-0402]  87.54 97.55 270 top
R159  0  [SM-7351-RES-0402]  139.61 114.97 180 top
R160  0  [SM-7351-RES-0402]  85.51 97.55 270 top
R161  0  [SM-7351-RES-0402]  139.61 113.58 180 top
R162  0  [SM-7351-RES-0402]  86.65 100.54 270 top
R163  0  [SM-7351-RES-0402]  139.61 112.18 180 top
R164  0  [SM-7351-RES-0402]  87.03 97.57 270 bottom
R165  0  [SM-7351-RES-0402]  139.61 110.91 180 top
R166  0  [SM-7351-RES-0402]  88.68 97.55 270 top
R167  0  [SM-7351-RES-0402]  139.61 109.64 180 top
R168  0  [SM-7351-RES-0402]  83.2 97.62 270 top
R169  0  [SM-7351-RES-0402]  139.61 108.24 180 top
R170  0  [SM-7351-RES-0402]  83.22 100.04 270 top
R171  0  [SM-7351-RES-0402]  139.61 106.84 180 top
R172  0  [SM-7351-RES-0402]  86.52 97.55 270 top
R173  0  [SM-7351-RES-0402]  100.88 92.75 0 top
R174  0  [SM-7351-RES-0402]  85.64 100.52 270 top
R175  0  [SM-7351-RES-0402]  99.71 89.09 270 top
R176  0  [SM-7351-RES-0402]  131.23 95.8 270 top
R177  0  [SM-7351-RES-0402]  69.51 94.27 90 top
R178  0  [SM-7351-RES-0402]  130.85 93.89 0 bottom
R179  0  [SM-7351-RES-0402]  139.61 102.78 0 top
R180  0  [SM-7351-RES-0402]  139.61 101.51 0 top
R181  0  [SM-7351-RES-0402]  119.42 95.03 180 top
R182  0  [SM-7351-RES-0402]  139.61 98.34 0 top
R183  0  [SM-7351-RES-0402]  139.61 97.07 0 top
R184  0  [SM-7351-RES-0402]  139.61 95.8 0 top
R185  0  [SM-7351-RES-0402]  88.05 97.57 270 bottom
R186  0  [SM-7351-RES-0402]  96.43 143.19 90 top
R187  0  [SM-7351-RES-0402]  93.89 143.22 90 top
R188  22  [SM-7351-RES-0402]  84.24 101.38 90 bottom
R189  0  [SM-7351-RES-0402]  139.61 104.18 0 top
R190  22  [SM-7351-RES-0402]  89.7 97.55 90 top
R191  0  [SM-7351-RES-0402]  139.61 105.57 0 top
R192  22  [SM-7351-RES-0402]  88.43 133.46 90 top
R193  0  [SM-7351-RES-0402]  88.68 121.96 270 top
R194  33  [SM-7351-RES-0402]  87.54 121.96 270 top
R195  22  [SM-7351-RES-0402]  87.29 133.41 90 top
R196  0  [SM-7351-RES-0402]  86.14 121.96 270 top
R197  0  [SM-7351-RES-0402]  83.6 143.04 90 bottom
R198  0  [SM-7351-RES-0402]  83.73 121.96 270 top
R199  0  [SM-7351-RES-0402]  82.46 123.35 90 bottom
R200  0  [SM-7351-RES-0402]  81.19 143.04 90 bottom
R201  0  [SM-7351-RES-0402]  71.03 94.27 180 top
R202  0  [SM-7351-RES-0402]  81.19 121.96 270 top
R203  0  [SM-7351-RES-0402]  79.92 123.35 90 bottom
R204  0  [SM-7351-RES-0402]  78.65 142.94 90 bottom
R205  0  [SM-7351-RES-0402]  79.16 134.28 180 top
R206  0  [SM-7351-RES-0402]  92.24 112.28 270 top
R207  0  [SM-7351-RES-0402]  76.11 141.9 90 bottom
R208  0  [SM-7351-RES-0402]  71.28 92.75 90 top
R209  0  [SM-7351-RES-0402]  90.97 112.28 270 top
R210  0  [SM-7351-RES-0402]  73.57 133.51 90 top
R211  0  [SM-7351-RES-0402]  71.16 112.18 180 top
R212  0  [SM-7351-RES-0402]  71.03 142.94 90 bottom
R213  0  [SM-7351-RES-0402]  79.79 104.18 90 top
R214  0  [SM-7351-RES-0402]  93.38 112.28 270 top
R215  0  [SM-7351-RES-0402]  68.49 142.94 90 bottom
R216  0  [SM-7351-RES-0402]  80.17 99.73 0 top
R217  0  [SM-7351-RES-0402]  86.52 112.28 270 top
R218  0  [SM-7351-RES-0402]  77.89 106.97 270 top
R219  0  [SM-7351-RES-0402]  66.97 142.89 90 bottom
R220  0  [SM-7351-RES-0402]  80.68 98.08 0 top
R221  0  [SM-7351-RES-0402]  66.71 95.54 270 top
R222  0  [SM-7351-RES-0402]  72.55 97.83 90 top
R223  0  [SM-7351-RES-0402]  88.81 112.28 270 top
R224  0  [SM-7351-RES-0402]  73.19 102.27 180 top
R225  0  [SM-7351-RES-0402]  74.71 104.18 180 top
R226  0  [SM-7351-RES-0402]  59.6 130.72 90 bottom
R227  0  [SM-7351-RES-0402]  59.47 122.08 270 top
R228  0  [SM-7351-RES-0402]  64.93 91.6 180 top
R229  0  [SM-7351-RES-0402]  75.73 100.49 180 top
R230  0  [SM-7351-RES-0402]  90.5 133.54 0 top
R231  22  [SM-7351-RES-0402]  81.77 101.18 90 top
R232  0  [SM-7351-RES-0402]  73.19 99.73 0 top
R233  0  [SM-7351-RES-0402]  56.07 123.1 270 bottom
R234  0  [SM-7351-RES-0402]  46.39 114.59 0 top
R235  22  [SM-7351-RES-0402]  53.25 133.64 270 top
R236  0  [SM-7351-RES-0402]  75.35 97.32 0 top
R237  22  [SM-7351-RES-0402]  83.22 105.07 90 top
R238  22  [SM-7351-RES-0402]  84.37 97.57 270 top
R239  10K  [SM-7351-RES-0402]  128.18 79.79 180 top
R240  0  [SM-7351-RES-0402]  140.37 86.02 0 top
R241  0  [SM-7351-RES-0402]  140.37 87.03 0 top
R242  0  [SM-7351-RES-0402]  109.51 86.27 90 top
R243  0  [SM-7351-RES-0402]  110.65 83.22 90 top
R244  0  [SM-7351-RES-0402]  72.55 96.81 90 top
R245  0  [SM-7351-RES-0402]  140.37 83.6 0 top
R246  0  [SM-7351-RES-0402]  140.37 84.62 0 top
R247  0  [SM-7351-RES-0402]  97.07 89.37 90 top
R248  0  [SM-7351-RES-0402]  100.88 94.27 180 top
R249  0  [SM-7351-RES-0402]  52.23 62.01 90 top
R250  0  [SM-7351-RES-0402]  63.92 91.6 0 top
R251  0  [SM-7351-RES-0402]  140.37 81.57 0 top
R252  0  [SM-7351-RES-0402]  140.37 82.59 0 top
R253  0  [SM-7351-RES-0402]  97.07 93.46 90 top
R254  0  [SM-7351-RES-0402]  128.18 83.86 180 top
R255  0  [SM-7351-RES-0402]  73.57 132.5 90 top
R256  0  [SM-7351-RES-0402]  140.37 79.54 0 top
R257  0  [SM-7351-RES-0402]  140.37 80.56 0 top
R258  0  [SM-7351-RES-0402]  128.18 81.83 180 top
R259  0  [SM-7351-RES-0402]  128.18 82.84 180 top
R260  0  [SM-7351-RES-0402]  140.37 78.4 0 top
R261  0  [SM-7351-RES-0402]  106.46 92.11 90 top
R262  0  [SM-7351-RES-0402]  128.18 80.81 180 top
R263  0  [SM-7351-RES-0402]  104.05 92.11 90 top
R264  0  [SM-7351-RES-0402]  112.05 86.27 90 top
R265  0  [SM-7351-RES-0402]  146.34 71.79 180 top
R266  0  [SM-7351-RES-0402]  128.18 78.78 180 top
R267  0  [SM-7351-RES-0402]  140.37 77.13 0 top
R268  0  [SM-7351-RES-0402]  146.34 70.52 180 top
R269  0  [SM-7351-RES-0402]  128.18 76.75 180 top
R270  0  [SM-7351-RES-0402]  128.18 77.76 180 top
R271  0  [SM-7351-RES-0402]  140.37 74.97 0 top
R272  0  [SM-7351-RES-0402]  128.18 74.71 180 top
R273  0  [SM-7351-RES-0402]  128.18 75.73 180 top
R274  10K  [SM-7351-RES-0402]  140.37 75.98 180 top
R361  0  [SM-7351-RES-0402]  72.05 97.32 0 top
R362  0  [SM-7351-RES-0402]  79.67 100.24 270 top
R363  0  [SM-7351-RES-0402]  79.67 98.08 0 top
R364  0  [SM-7351-RES-0402]  79.29 103.67 0 top
R365  10K  [SM-7351-RES-0402]  46.39 148.37 90 bottom
R366  10K  [SM-7351-RES-0402]  48.55 148.37 90 bottom
R367  10K  [SM-7351-RES-0402]  50.84 148.37 90 bottom
R368  10K  [SM-7351-RES-0402]  49.69 148.37 90 bottom
R369  10K  [SM-7351-RES-0402]  43.85 148.37 90 bottom
R370  10K  [SM-7351-RES-0402]  47.66 165.77 90 bottom
R371  10K  [SM-7351-RES-0402]  50.08 165.77 90 bottom
R372  10K  [SM-7351-RES-0402]  57.57 165.77 90 bottom
R373  10K  [SM-7351-RES-0402]  60.11 165.77 90 bottom
R378  470K  [SM-7351-RES-0402]  63.16 144.69 90 top
R379  0  [SM-7351-RES-0402]  77.38 106.46 0 top
R380  0  [SM-7351-RES-0402]  72.3 91.67 90 top
R381  120K  [SM-7351-RES-0402]  134.15 162.19 270 top
R382  10K  [SM-7351-RES-0402]  138.98 150.72 270 top
R383  10K  [SM-7351-RES-0402]  137.32 145.13 90 bottom
R384  0  [SM-7351-RES-0402]  91.52 133.54 0 top
R385  0  [SM-7351-RES-0402]  149.77 161.52 270 top
R386  100K  [SM-7351-RES-0402]  156.88 144.18 270 top
R387  10K  [SM-7351-RES-0402]  145.64 144.69 270 bottom
R396  0  [SM-7351-RES-0402]  66.97 143.9 270 bottom
R397  0  [SM-7351-RES-0402]  81.19 144.06 270 bottom
R398  0  [SM-7351-RES-0402]  83.6 144.06 270 bottom
R399  0  [SM-7351-RES-0402]  78.65 143.95 270 bottom
R400  0  [SM-7351-RES-0402]  71.03 143.95 270 bottom
R401  0  [SM-7351-RES-0402]  68.49 143.95 270 bottom
R410  0  [SM-7351-RES-0402]  84.75 100.88 0 bottom
R412  10K  [SM-7351-RES-0402]  146.91 152.63 270 top
R429  22  [SM-7351-RES-0402]  87.92 72.94 270 bottom
R453  4.7K  [SM-7351-RES-0402]  73.57 40.93 270 bottom
R454  4.7K  [SM-7351-RES-0402]  71.03 40.8 270 bottom
R455  10K  [SM-7351-RES-0402]  65.95 40.55 270 bottom
R463  0  [SM-7351-RES-0603]  96.05 26.45 180 top
R464  0  [SM-7351-RES-0603]  90.97 26.71 90 bottom
R465  0  [SM-7351-RES-0603]  99.48 28.1 180 top
R466  0  [SM-7351-RES-0603]  96.05 28.1 0 top
R467  0  [SM-7351-RES-0603]  103.16 28.1 180 top
R468  0  [SM-7351-RES-0603]  77.25 36.11 270 top
R469  0  [SM-7351-RES-0603]  81.19 43.09 270 top
R470  0  [SM-7351-RES-0603]  92.49 44.49 270 top
R471  0  [SM-7351-RES-0603]  97.83 36.11 0 top
R472  0  [SM-7351-RES-0603]  112.05 47.92 90 bottom
R473  0  [SM-7351-RES-0603]  97.83 37.88 0 top
R474  0  [SM-7351-RES-0603]  82.71 30.77 180 top
R475  0  [SM-7351-RES-0603]  82.71 29.25 180 top
R476  0  [SM-7351-RES-0603]  90.46 27.47 180 top
R477  0  [SM-7351-RES-0603]  82.71 27.72 0 top
R493  0.24ohm1% Sense  [SM_RES_0805_KELV]  120.81 69.51 180 bottom
R494  0.24ohm1% Sense  [SM_RES_0805_KELV]  134.78 131.86 270 bottom
R495  0.24ohm1% Sense  [SM_RES_0805_KELV]  101.76 141.26 0 bottom
R496  0.24ohm1% Sense  [SM_RES_0805_KELV]  51.66 86.91 0 bottom
R497  2ohm1% Sense  [SM_RES_0805_KELV]  95.67 115.73 180 top
R498  0.24ohm1% Sense  [SM_RES_0805_KELV]  101.89 115.48 0 bottom
R499  2ohm1% Sense  [SM_RES_0805_KELV]  48.68 96.18 90 bottom
R500  2ohm1% Sense  [SM_RES_0805_KELV]  48.68 101.89 90 bottom
R501  1ohm1% Sense  [SM_RES_0805_KELV]  47.92 75.73 90 bottom
R502  1ohm1% Sense  [SM_RES_0805_KELV]  115.99 141.13 180 top
R503  2ohm1% Sense  [SM_RES_0805_KELV]  106.21 63.79 180 bottom
R504  2ohm1% Sense  [SM_RES_0805_KELV]  108.88 141.13 180 top
R505  2ohm1% Sense  [SM_RES_0805_KELV]  61.31 49.31 180 bottom
R506  2ohm1% Sense  [SM_RES_0805_KELV]  113.45 63.79 180 bottom
R507  2ohm1% Sense  [SM_RES_0805_KELV]  61.25 55.03 180 bottom
R508  0.24ohm1% Sense  [SM_RES_0805_KELV]  113.26 69.44 0 top
R509  0  [SM-7351-RES-0402]  90.46 111.77 0 top
R510  0  [SM-7351-RES-0402]  86.02 111.77 0 top
R511  0  [SM-7351-RES-0402]  88.3 111.77 0 top
R512  0  [SM-7351-RES-0402]  59.6 131.74 270 bottom
R517  100  [SM-7351-RES-0402]  20.48 87.41 270 top
R520  1.62M  [SM-7351-RES-0402]  153.07 145.2 180 top
R521  180K  [SM-7351-RES-0402]  153.07 144.18 0 top
R522  22  [SM-7351-RES-0402]  88.94 72.94 270 bottom
R523  22  [SM-7351-RES-0402]  91.67 72.62 270 top
R524  22  [SM-7351-RES-0402]  92.62 72.62 270 top
R525  22  [SM-7351-RES-0402]  90.59 73.06 180 bottom
R526  22  [SM-7351-RES-0402]  90.72 75.6 270 bottom
R527  22  [SM-7351-RES-0402]  92.24 72.68 270 bottom
R528  22  [SM-7351-RES-0402]  93.38 72.3 270 bottom
R529  22  [SM-7351-RES-0402]  85 72.62 270 top
R530  22  [SM-7351-RES-0402]  85.95 72.62 270 top
R531  22  [SM-7351-RES-0402]  86.91 72.62 270 top
R532  22  [SM-7351-RES-0402]  84.05 75.16 270 bottom
R533  22  [SM-7351-RES-0402]  85.95 75.16 270 bottom
R534  22  [SM-7351-RES-0402]  86.91 75.16 270 bottom
R535  22  [SM-7351-RES-0402]  86.91 72.94 270 bottom
R536  22  [SM-7351-RES-0402]  89.76 72.62 270 top
R537  22  [SM-7351-RES-0402]  79.29 75.16 270 bottom
R538  22  [SM-7351-RES-0402]  84.05 72.62 270 top
R539  22  [SM-7351-RES-0402]  95.48 72.62 270 top
R540  22  [SM-7351-RES-0402]  88.81 72.62 270 top
R541  2.2K  [SM-7351-RES-0402]  85 79.29 90 bottom
R542  2.2K  [SM-7351-RES-0402]  94.53 67.22 180 top
R543  22  [SM-7351-RES-0402]  82.14 72.62 270 top
R544  10K  [SM-7351-RES-0402]  59.28 35.47 180 top
R545  0.24ohm1% Sense  [SM_RES_0805_KELV]  112.94 94.84 180 bottom
R546  0.24ohm1% Sense  [SM_RES_0805_KELV]  133.58 139.29 270 top
R547  4.7K  [SM-7351-RES-0402]  78.52 97.57 90 bottom
R548  4.7K  [SM-7351-RES-0402]  77.38 97.57 90 bottom
R549  22  [SM-7351-RES-0402]  73.19 76.62 270 top
R550  0  [SM-7351-RES-0402]  83.22 26.2 180 bottom
R551  0  [SM-7351-RES-0402]  83.22 25.06 180 bottom
R552  4.7K  [SM-7351-RES-0402]  72.17 96.68 90 bottom
R553  4.7K  [SM-7351-RES-0402]  71.03 96.68 90 bottom
R554  4.7K  [SM-7351-RES-0402]  77.76 101.13 90 bottom
R555  4.7K  [SM-7351-RES-0402]  78.9 101.13 90 bottom
R556  0  [SM-7351-RES-0402]  85.51 31.79 0 bottom
R557  0  [SM-7351-RES-0603]  84.11 25.31 180 top
R558  0  [SM-7351-RES-0603]  153.33 160.44 0 top
R559  0  [SM-7351-RES-0402]  10.83 46.9 90 bottom
R560  0  [SM-7351-RES-0402]  9.05 46.39 0 bottom
R561  0  [SM-7351-RES-0402]  73.19 78.27 180 top
R562  0  [SM-7351-RES-0402]  88.81 40.55 270 top
R563  1.2K, 1/4W  [SM-7351-RES-0805]  96.3 98.46 270 top
R564  1.2K, 1/4W  [SM-7351-RES-0805]  90.59 104.05 270 top
R565  10K  [SM-7351-RES-0402]  125.26 161.07 270 top
R566  0  [SM-7351-RES-0402]  125.26 163.49 90 top
R571  0  [SM-7351-RES-0402]  130.06 159.02 90 top
R572  0  [SM-7351-RES-0402]  117.2 95.03 180 top
R573  0  [SM-7351-RES-0402]  93.89 145.27 90 top
R574  0  [SM-7351-RES-0402]  85.13 120.81 270 top
R575  0  [SM-7351-RES-0402]  82.71 120.81 270 top
R576  0  [SM-7351-RES-0402]  80.17 120.81 270 top
R577  0  [SM-7351-RES-0402]  97.57 143.22 270 top
SW1  Slide Switch  [TH_SW_T551101]  75.6 10.2 90 top
SW2  B3SL  [SW_B3SL-1022P]  8.8 62.14 270 top
SW3  Switch8pos  [219-8MST]  159.93 60.24 270 top
SW4  Switch8pos  [219-8MST]  159.93 82.84 270 top
SW5  B3SL  [SW_B3SL-1022P]  8.8 44.36 270 top
TP2  TP1mm  [TP_SMD1MMCIRCLE]  83.03 76.75 180 bottom
TP23  TP1mm  [TP_SMD1MMCIRCLE]  93.13 98.59 0 top
TP24  TP1mm  [TP_SMD1MMCIRCLE]  69.25 78.02 270 top
TP25  TP  [TH_TP_5002]  88.81 20.36 0 top
TP26  TP  [TH_TP_5002]  100.88 42.07 180 top
TP27  TP  [TH_TP_5002]  8.17 93.51 0 top
TP28  TP  [TH_TP_5002]  167.55 91.35 0 top
TP29  TP  [TH_TP_5002]  91.86 2.7 0 top
TP30  TP  [TH_TP_5002]  85 167.55 0 top
TP35  TP1mm  [TP_SMD1MMCIRCLE]  77.38 122.85 180 bottom
TP36  TP1mm  [TP_SMD1MMCIRCLE]  91.35 96.3 0 top
TP38  TP1mm  [TP_SMD1MMCIRCLE]  43.47 61.38 0 top
TP39  TP1mm  [TP_SMD1MMCIRCLE]  43.47 59.98 0 top
TP40  TP1mm  [TP_SMD1MMCIRCLE]  43.47 57.82 0 top
TP41  TP1mm  [TP_SMD1MMCIRCLE]  43.47 56.43 0 top
U1  SN74AUP2G08  [U_8_DCU]  62.9 100.11 270 top
U2  AM335X_15x15  [AM33XX_15X15]  85 85 90 top
U4  TPS65910  [U_48_RSL]  89.45 33.69 90 top
U5  TPS71718  [SMDSC70-5]  84.11 22.52 0 top
U6  SN74AUP2G08  [U_8_DCU]  90.21 23.53 270 top
U7  CAT24C256W  [SOIC_8]  140.31 67.89 0 top
U8  MT47H256M8  [DDR2_FBGA60PIN]  72.94 60.24 270 top
U9  MT29F2G08AB  [SKT-TSOP48SM]  149.01 106.59 90 top
U18  MAX3232E  [U_16_D]  109.51 18.58 270 top
U19  TPD6E001  [U_10_RSE]  58.46 144.06 0 top
U20  TPD6E001  [U_10_RSE]  71.92 149.77 90 top
U21  TPD2E001  [U_5_DRL]  64.93 144.56 270 top
U22  TPS2051BD  [U_8_D]  135.42 147.55 0 top
U23  TPD4S012  [U_6_DRY]  132.37 162.32 0 top
U24  TPS63010  [U_20_DSBGA]  155.99 146.85 90 top
U27  INA226  [SMDMSOP_10]  69.13 47.03 270 bottom
U29  TPS2051BD  [U_8_D]  143.74 147.23 0 top
U30  TPD4S012  [U_6_DRY]  147.93 161.45 0 top
U31  MT47H256M8  [DDR2_FBGA60PIN]  95.16 60.24 270 top
U32  INA226  [SMDMSOP_10]  64.36 35.15 270 top
Y1  32.768KHz MC-306  [MC-306]  63.03 76.36 270 top
Y2  24MHz  [SM_CRY_SCC18]  105.7 81.83 0 top

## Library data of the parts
BT1 = Battery_coin3V
C1 C16 C17 C19 C23-C25 C29-C32 C35 C36 C43 C45-C48 C50 C52 C53 C61 C62 = 0.01uFCapacitor16V10%0402
C2 C3 = 25pFCapacitor100V5%0603
C4 C5 = 18pFCapacitor16V10%0402
C9 = 0.1uFCapacitor16V10%0402
C10 C12 = 0.001uFCapacitor50V5%0402
C11 C13 C85 C86 C98 C127 C131-C135 C141 C148 C176-C180 C187 C260 C264 = 0.1uFCapacitor16V10%0402: Tolerance: TOLERANCE; User Part Number: USERPART#
C14 = 0.001uFCapacitor50V5%0402: Tolerance: TOLERANCE; User Part Number: USERPART#
C27 C28 C34 C41 C42 C56 C63 C64 C66-C70 C73 C76-C80 C82 C83 C89 C90 C92-C94 C96 C111 C114-C116 C125 C126 C128-C130 C136-C140 C155 C156 C174 C175 C181 C183 C186 C188 C189 C195 C202 C215-C222 = 0.01uFCapacitor16V10%0402: Tolerance: TOLERANCE; User Part Number: USERPART#
C60 = 1uFCapacitor16V10%0402
C65 C71 C72 C88 C112 C113 C117 C118 = 1uFCapacitor16V10%0402: Tolerance: TOLERANCE; User Part Number: USERPART#
C84 = 100uFCapacitor16V20%ElectroPoly
C91 C97 C101-C104 C107-C110 C184 = 2.2uFCapacitor6.3V20%smdX5R0402: Tolerance: TOLERANCE; User Part Number: USERPART#
C182 C185 = 150uFCapacitor10V10%2917
C232-C241 C245-C247 C249 C257-C259 C261 C273 C274 = 10uFCapacitor16V10%0805
C250-C255 = 4.7uFCapacitor6.3V20%smdX5R0603
C262 C263 C265 = 4.7uFCapacitor16V10%0603
C266 C267 C269 C270 = 22uFCapacitor16V10%0805
D1 = Diode_5ARect
D2 = Diode_SMCJ15CA
D3-D7 = LED_Green
D9 D10 = Diode_Zener_5.1V_100mW
F1 = Fuse_4A
FB1-FB10 FB14 FB19-FB21 = FerBead_180ohm200mA
J1 = Conn_PwrJack_RAPC712
J2 = Header10x2_CJTAG
J3 J4 J6 = Header_28pin_0.1in
J5 = Header_40pin_0.1in
J7-J9 = Header10x2_0.5inpitch_female
J12 = Conn_DSUB9M_TH
J13 = Conn_SDCard_MHC-W21-601
J14 = Conn_MicroUSBAB
J17 = Header_5x1
J18 = Connector_USB_A
J19 = Header20x1_wkey
J20-J39 = Header_2x1
L2-L4 = 2.2uHInductor10%2.6Asmd
L5 L6 = ACM2012
L8 = 4.7uH30%0.9Asmd
L9 = 4.7uHInductor30%3.1Asmd
Q1-Q4 = MOSFET_NChan_BSS138
Q5 = MOSFET_PChan_BSS84
R1 R3 R5 R8-R10 R30 R45 R51 R53 R55-R64 R66 R68 R73-R78 R84 R85 R87-R92 R113 R133-R187 R189 R191 R193 R196-R230 R232-R234 R236 R240-R273 R361-R364 R379 R380 R384 R385 R396-R401 R410 R509-R512 R550 R551 R556 R559-R562 R566 R571-R577 = ZeroOhmResistor1/16W0402
R2 R4 R86 R93-R95 R102-R110 R386 = 100KOhmResistor1/16W0402
R6 R48 R54 R65 R72 R120-R128 R130-R132 R239 R274 R365-R373 R382 R383 R387 R412 R455 R544 R565 = 10KOhmResistor1/16W0402
R7 = 1MOhmResistor1/16W0402
R11-R21 R31 R33-R44 R47 R49 R429 R522-R540 R543 R549 = 22OhmResistor1/16W1%0402: signal model: 33OHMRESISTOR1_16W5_0402_SM_735_33
R22 = 50OhmResistor1/16W1%0402
R23 = 124Kohm1/16W1%SMD0402
R32 R46 = 0.05ohm0.5W1%Sense1206
R50 R80-R83 = 150ohm1/16W1%SMD0402
R69 R112 R114-R119 R129 = 1KOhmResistor1/16W0402
R70 R71 R79 R453 R454 R547 R548 R552-R555 = 4.7KOhmResistor1/16W0402
R96-R101 R111 = 9.1KohmResistor1/16W1%0402
R188 R190 R192 R195 R231 R235 R237 R238 = 22OhmResistor1/16W1%0402
R194 = 33ohmResistor1/16W5%0402
R378 = 470Kohm1/16W1%SMD0402
R381 = 120Kohm1/16W1%SMD0402
R463-R477 R557 R558 = ZeroOhmResistor1/16W0603
R493-R496 R498 R508 R545 R546 = 0.24ohm0.25W1%Sense0805
R497 R499 R500 R503-R507 = 2ohm0.25W1%Sense0805
R501 R502 = 1ohm0.25W1%Sense0805
R517 = 100ohm1/16W1%SMD0402
R520 = 1.62MOhmResistor1/16W0402
R521 = 180KOhmResistor1/16W0402
R541 R542 = 2.2KOhmResistor1/16W0402
R563 R564 = 1.2KohmResistor1/4W5%0805
SW1 = Switch_SlideRA_SPDT
SW2 SW5 = Switch_Pushbuttonsmd
SW3 SW4 = SwitchDIP8pos_smd
TP2 TP23 TP24 TP35 TP36 TP38-TP41 = Testpoint_SMD1mmCircle
TP25-TP30 = TestPointThroughHole
U1 U6 = SN74AUP2G08
U2 = AM335X_15mmx15mm
U4 = TPS65910
U5 = TPS71718
U7 = CAT24C256W
U8 U31 = MT47H256M8
U9 = MT29F2G08ABBE
U18 = MAX3232E
U19 U20 = TPD6E001RSE
U21 = TPD2E001DRL
U22 U29 = TPS2051BD
U23 U30 = TPD4S012
U24 = TPS63010YFF
U27 U32 = INA226
Y1 = Crystal_SMD32_768kHz
Y2 = Crystal24MHzSCC

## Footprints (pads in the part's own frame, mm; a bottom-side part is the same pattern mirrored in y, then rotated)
219-8MST
  rect 1.118x2.438 smd: 1(-8.89,-4.318) 2(-6.35,-4.318) 3(-3.81,-4.318) 4(-1.27,-4.318) 5(1.27,-4.318) 6(3.81,-4.318) 7(6.35,-4.318) 8(8.89,-4.318) 9(8.89,4.318) 10(6.35,4.318) 11(3.81,4.318) 12(1.27,4.318) 13(-1.27,4.318) 14(-3.81,4.318) 15(-6.35,4.318) 16(-8.89,4.318)
ACM2012H
  rect 0.75x0.35 smd: 1(-0.975,0.425) 2(-0.975,-0.425) 3(0.975,-0.425) 4(0.975,0.425)
AM33XX_15X15
  round 1.27 hole 1.778 unplated: (-9.238,8.863) (-9.238,-8.862) (8.487,8.863) (8.487,-8.862)
  round 1.397 hole 0.838 unplated: (-9.238,-3.782) (8.487,6.323)
  round 0.356 smd: A1(-6.8,6.8) A2(-6,6.8) A3(-5.2,6.8) A4(-4.4,6.8) A5(-3.6,6.8) A6(-2.8,6.8) A7(-2,6.8) A8(-1.2,6.8) A9(-0.4,6.8) A10(0.4,6.8) A11(1.2,6.8) A12(2,6.8) A13(2.8,6.8) A14(3.6,6.8) A15(4.4,6.8) A16(5.2,6.8) A17(6,6.8) A18(6.8,6.8) B1(-6.8,6) B2(-6,6) B3(-5.2,6) B4(-4.4,6) B5(-3.6,6) B6(-2.8,6) B7(-2,6) B8(-1.2,6) B9(-0.4,6) B10(0.4,6) B11(1.2,6) B12(2,6) B13(2.8,6) B14(3.6,6) B15(4.4,6) B16(5.2,6) B17(6,6) B18(6.8,6) C1(-6.8,5.2) C2(-6,5.2) C3(-5.2,5.2) C4(-4.4,5.2) C5(-3.6,5.2) C6(-2.8,5.2) C7(-2,5.2) C8(-1.2,5.2) C9(-0.4,5.2) C10(0.4,5.2) C11(1.2,5.2) C12(2,5.2) C13(2.8,5.2) C14(3.6,5.2) C15(4.4,5.2) C16(5.2,5.2) C17(6,5.2) C18(6.8,5.2) D1(-6.8,4.4) D2(-6,4.4) D3(-5.2,4.4) D4(-4.4,4.4) D5(-3.6,4.4) D6(-2.8,4.4) D7(-2,4.4) D8(-1.2,4.4) D9(-0.4,4.4) D10(0.4,4.4) D11(1.2,4.4) D12(2,4.4) D13(2.8,4.4) D14(3.6,4.4) D15(4.4,4.4) D16(5.2,4.4) D17(6,4.4) D18(6.8,4.4) E1(-6.8,3.6) E2(-6,3.6) E3(-5.2,3.6) E4(-4.4,3.6) E5(-3.6,3.6) E6(-2.8,3.6) E7(-2,3.6) E8(-1.2,3.6) E9(-0.4,3.6) E10(0.4,3.6) E11(1.2,3.6) E12(2,3.6) E13(2.8,3.6) E14(3.6,3.6) E15(4.4,3.6) E16(5.2,3.6) E17(6,3.6) E18(6.8,3.6) F1(-6.8,2.8) F2(-6,2.8) F3(-5.2,2.8) F4(-4.4,2.8) F5(-3.6,2.8) F6(-2.8,2.8) F7(-2,2.8) F8(-1.2,2.8) F9(-0.4,2.8) F10(0.4,2.8) F11(1.2,2.8) F12(2,2.8) F13(2.8,2.8) F14(3.6,2.8) F15(4.4,2.8) F16(5.2,2.8) F17(6,2.8) F18(6.8,2.8) G1(-6.8,2) G2(-6,2) G3(-5.2,2) G4(-4.4,2) G5(-3.6,2) G6(-2.8,2) G7(-2,2) G8(-1.2,2) G9(-0.4,2) G10(0.4,2) G11(1.2,2) G12(2,2) G13(2.8,2) G14(3.6,2) G15(4.4,2) G16(5.2,2) G17(6,2) G18(6.8,2) H1(-6.8,1.2) H2(-6,1.2) H3(-5.2,1.2) H4(-4.4,1.2) H5(-3.6,1.2) H6(-2.8,1.2) H7(-2,1.2) H8(-1.2,1.2) H9(-0.4,1.2) H10(0.4,1.2) H11(1.2,1.2) H12(2,1.2) H13(2.8,1.2) H14(3.6,1.2) H15(4.4,1.2) H16(5.2,1.2) H17(6,1.2) H18(6.8,1.2) J1(-6.8,0.4) J2(-6,0.4) J3(-5.2,0.4) J4(-4.4,0.4) J5(-3.6,0.4) J6(-2.8,0.4) J7(-2,0.4) J8(-1.2,0.4) J9(-0.4,0.4) J10(0.4,0.4) J11(1.2,0.4) J12(2,0.4) J13(2.8,0.4) J14(3.6,0.4) J15(4.4,0.4) J16(5.2,0.4) J17(6,0.4) J18(6.8,0.4) K1(-6.8,-0.4) K2(-6,-0.4) K3(-5.2,-0.4) K4(-4.4,-0.4) K5(-3.6,-0.4) K6(-2.8,-0.4) K7(-2,-0.4) K8(-1.2,-0.4) K9(-0.4,-0.4) K10(0.4,-0.4) K11(1.2,-0.4) K12(2,-0.4) K13(2.8,-0.4) K14(3.6,-0.4) K15(4.4,-0.4) K16(5.2,-0.4) K17(6,-0.4) K18(6.8,-0.4) L1(-6.8,-1.2) L2(-6,-1.2) L3(-5.2,-1.2) L4(-4.4,-1.2) L5(-3.6,-1.2) L6(-2.8,-1.2) L7(-2,-1.2) L8(-1.2,-1.2) L9(-0.4,-1.2) L10(0.4,-1.2) L11(1.2,-1.2) L12(2,-1.2) L13(2.8,-1.2) L14(3.6,-1.2) L15(4.4,-1.2) L16(5.2,-1.2) L17(6,-1.2) L18(6.8,-1.2) M1(-6.8,-2) M2(-6,-2) M3(-5.2,-2) M4(-4.4,-2) M5(-3.6,-2) M6(-2.8,-2) M7(-2,-2) M8(-1.2,-2) M9(-0.4,-2) M10(0.4,-2) M11(1.2,-2) M12(2,-2) M13(2.8,-2) M14(3.6,-2) M15(4.4,-2) M16(5.2,-2) M17(6,-2) M18(6.8,-2) N1(-6.8,-2.8) N2(-6,-2.8) N3(-5.2,-2.8) N4(-4.4,-2.8) N5(-3.6,-2.8) N6(-2.8,-2.8) N7(-2,-2.8) N8(-1.2,-2.8) N9(-0.4,-2.8) N10(0.4,-2.8) N11(1.2,-2.8) N12(2,-2.8) N13(2.8,-2.8) N14(3.6,-2.8) N15(4.4,-2.8) N16(5.2,-2.8) N17(6,-2.8) N18(6.8,-2.8) P1(-6.8,-3.6) P2(-6,-3.6) P3(-5.2,-3.6) P4(-4.4,-3.6) P5(-3.6,-3.6) P6(-2.8,-3.6) P7(-2,-3.6) P8(-1.2,-3.6) P9(-0.4,-3.6) P10(0.4,-3.6) P11(1.2,-3.6) P12(2,-3.6) P13(2.8,-3.6) P14(3.6,-3.6) P15(4.4,-3.6) P16(5.2,-3.6) P17(6,-3.6) P18(6.8,-3.6) R1(-6.8,-4.4) R2(-6,-4.4) R3(-5.2,-4.4) R4(-4.4,-4.4) R5(-3.6,-4.4) R6(-2.8,-4.4) R7(-2,-4.4) R8(-1.2,-4.4) R9(-0.4,-4.4) R10(0.4,-4.4) R11(1.2,-4.4) R12(2,-4.4) R13(2.8,-4.4) R14(3.6,-4.4) R15(4.4,-4.4) R16(5.2,-4.4) R17(6,-4.4) R18(6.8,-4.4) T1(-6.8,-5.2) T2(-6,-5.2) T3(-5.2,-5.2) T4(-4.4,-5.2) T5(-3.6,-5.2) T6(-2.8,-5.2) T7(-2,-5.2) T8(-1.2,-5.2) T9(-0.4,-5.2) T10(0.4,-5.2) T11(1.2,-5.2) T12(2,-5.2) T13(2.8,-5.2) T14(3.6,-5.2) T15(4.4,-5.2) T16(5.2,-5.2) T17(6,-5.2) T18(6.8,-5.2) U1(-6.8,-6) U2(-6,-6) U3(-5.2,-6) U4(-4.4,-6) U5(-3.6,-6) U6(-2.8,-6) U7(-2,-6) U8(-1.2,-6) U9(-0.4,-6) U10(0.4,-6) U11(1.2,-6) U12(2,-6) U13(2.8,-6) U14(3.6,-6) U15(4.4,-6) U16(5.2,-6) U17(6,-6) U18(6.8,-6) V1(-6.8,-6.8) V2(-6,-6.8) V3(-5.2,-6.8) V4(-4.4,-6.8) V5(-3.6,-6.8) V6(-2.8,-6.8) V7(-2,-6.8) V8(-1.2,-6.8) V9(-0.4,-6.8) V10(0.4,-6.8) V11(1.2,-6.8) V12(2,-6.8) V13(2.8,-6.8) V14(3.6,-6.8) V15(4.4,-6.8) V16(5.2,-6.8) V17(6,-6.8) V18(6.8,-6.8)
B520C-13-F
  rect 2.5x3.3 smd: 1(-3.4,0) 2(3.4,0)
CHKFOOTPRINT
  rect 0.8x1.8 smd: 1(-0.8,0) 2(0.8,0)
DDR2_FBGA60PIN
  round 0.356 smd: A1(-3.2,4) A2(-2.4,4) A3(-1.6,4) A7(1.6,4) A8(2.4,4) A9(3.2,4) B1(-3.2,3.2) B2(-2.4,3.2) B3(-1.6,3.2) B7(1.6,3.2) B8(2.4,3.2) B9(3.2,3.2) C1(-3.2,2.4) C2(-2.4,2.4) C3(-1.6,2.4) C7(1.6,2.4) C8(2.4,2.4) C9(3.2,2.4) D1(-3.2,1.6) D2(-2.4,1.6) D3(-1.6,1.6) D7(1.6,1.6) D8(2.4,1.6) D9(3.2,1.6) E1(-3.2,0.8) E2(-2.4,0.8) E3(-1.6,0.8) E7(1.6,0.8) E8(2.4,0.8) E9(3.2,0.8) F2(-2.4,0) F3(-1.6,0) F7(1.6,0) F8(2.4,0) F9(3.2,0) G1(-3.2,-0.8) G2(-2.4,-0.8) G3(-1.6,-0.8) G7(1.6,-0.8) G8(2.4,-0.8) H2(-2.4,-1.6) H3(-1.6,-1.6) H7(1.6,-1.6) H8(2.4,-1.6) H9(3.2,-1.6) J1(-3.2,-2.4) J2(-2.4,-2.4) J3(-1.6,-2.4) J7(1.6,-2.4) J8(2.4,-2.4) K2(-2.4,-3.2) K3(-1.6,-3.2) K7(1.6,-3.2) K8(2.4,-3.2) K9(3.2,-3.2) L1(-3.2,-4) L2(-2.4,-4) L3(-1.6,-4) L7(1.6,-4) L8(2.4,-4)
GMD2_2PIN
  rect 0.31x0.23 smd: 1(0,-0.19) 2(0,0.19)
HEADER10X2
  rect 0.711x2.87 smd: 1(-5.715,-2.705) 2(-5.715,2.705) 3(-4.445,-2.705) 4(-4.445,2.705) 5(-3.175,-2.705) 6(-3.175,2.705) 7(-1.905,-2.705) 8(-1.905,2.705) 9(-0.635,-2.705) 10(-0.635,2.705) 11(0.635,-2.705) 12(0.635,2.705) 13(1.905,-2.705) 14(1.905,2.705) 15(3.175,-2.705) 16(3.175,2.705) 17(4.445,-2.705) 18(4.445,2.705) 19(5.715,-2.705) 20(5.715,2.705)
HEADER20X1_0_100IN
  rect 1.524x1.524 hole 1.016: 1(0,0)
  round 1.524 hole 1.016: 2(2.54,0) 3(5.08,0) 5(10.16,0) 6(12.7,0) 7(15.24,0) 8(17.78,0) 9(20.32,0) 10(22.86,0) 11(25.4,0) 12(27.94,0) 13(30.48,0) 14(33.02,0) 15(35.56,0) 16(38.1,0) 17(40.64,0) 18(43.18,0) 19(45.72,0) 20(48.26,0)
